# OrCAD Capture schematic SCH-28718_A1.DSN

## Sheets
1 1. Title Page: title: FRDM-KV10Z; rev: A1; company: Freescale Semiconductor; note: SCH-28718 | PDF: SPF-28718; note: 6501 William Cannon Drive West; note: Austin, TX 78735-8598
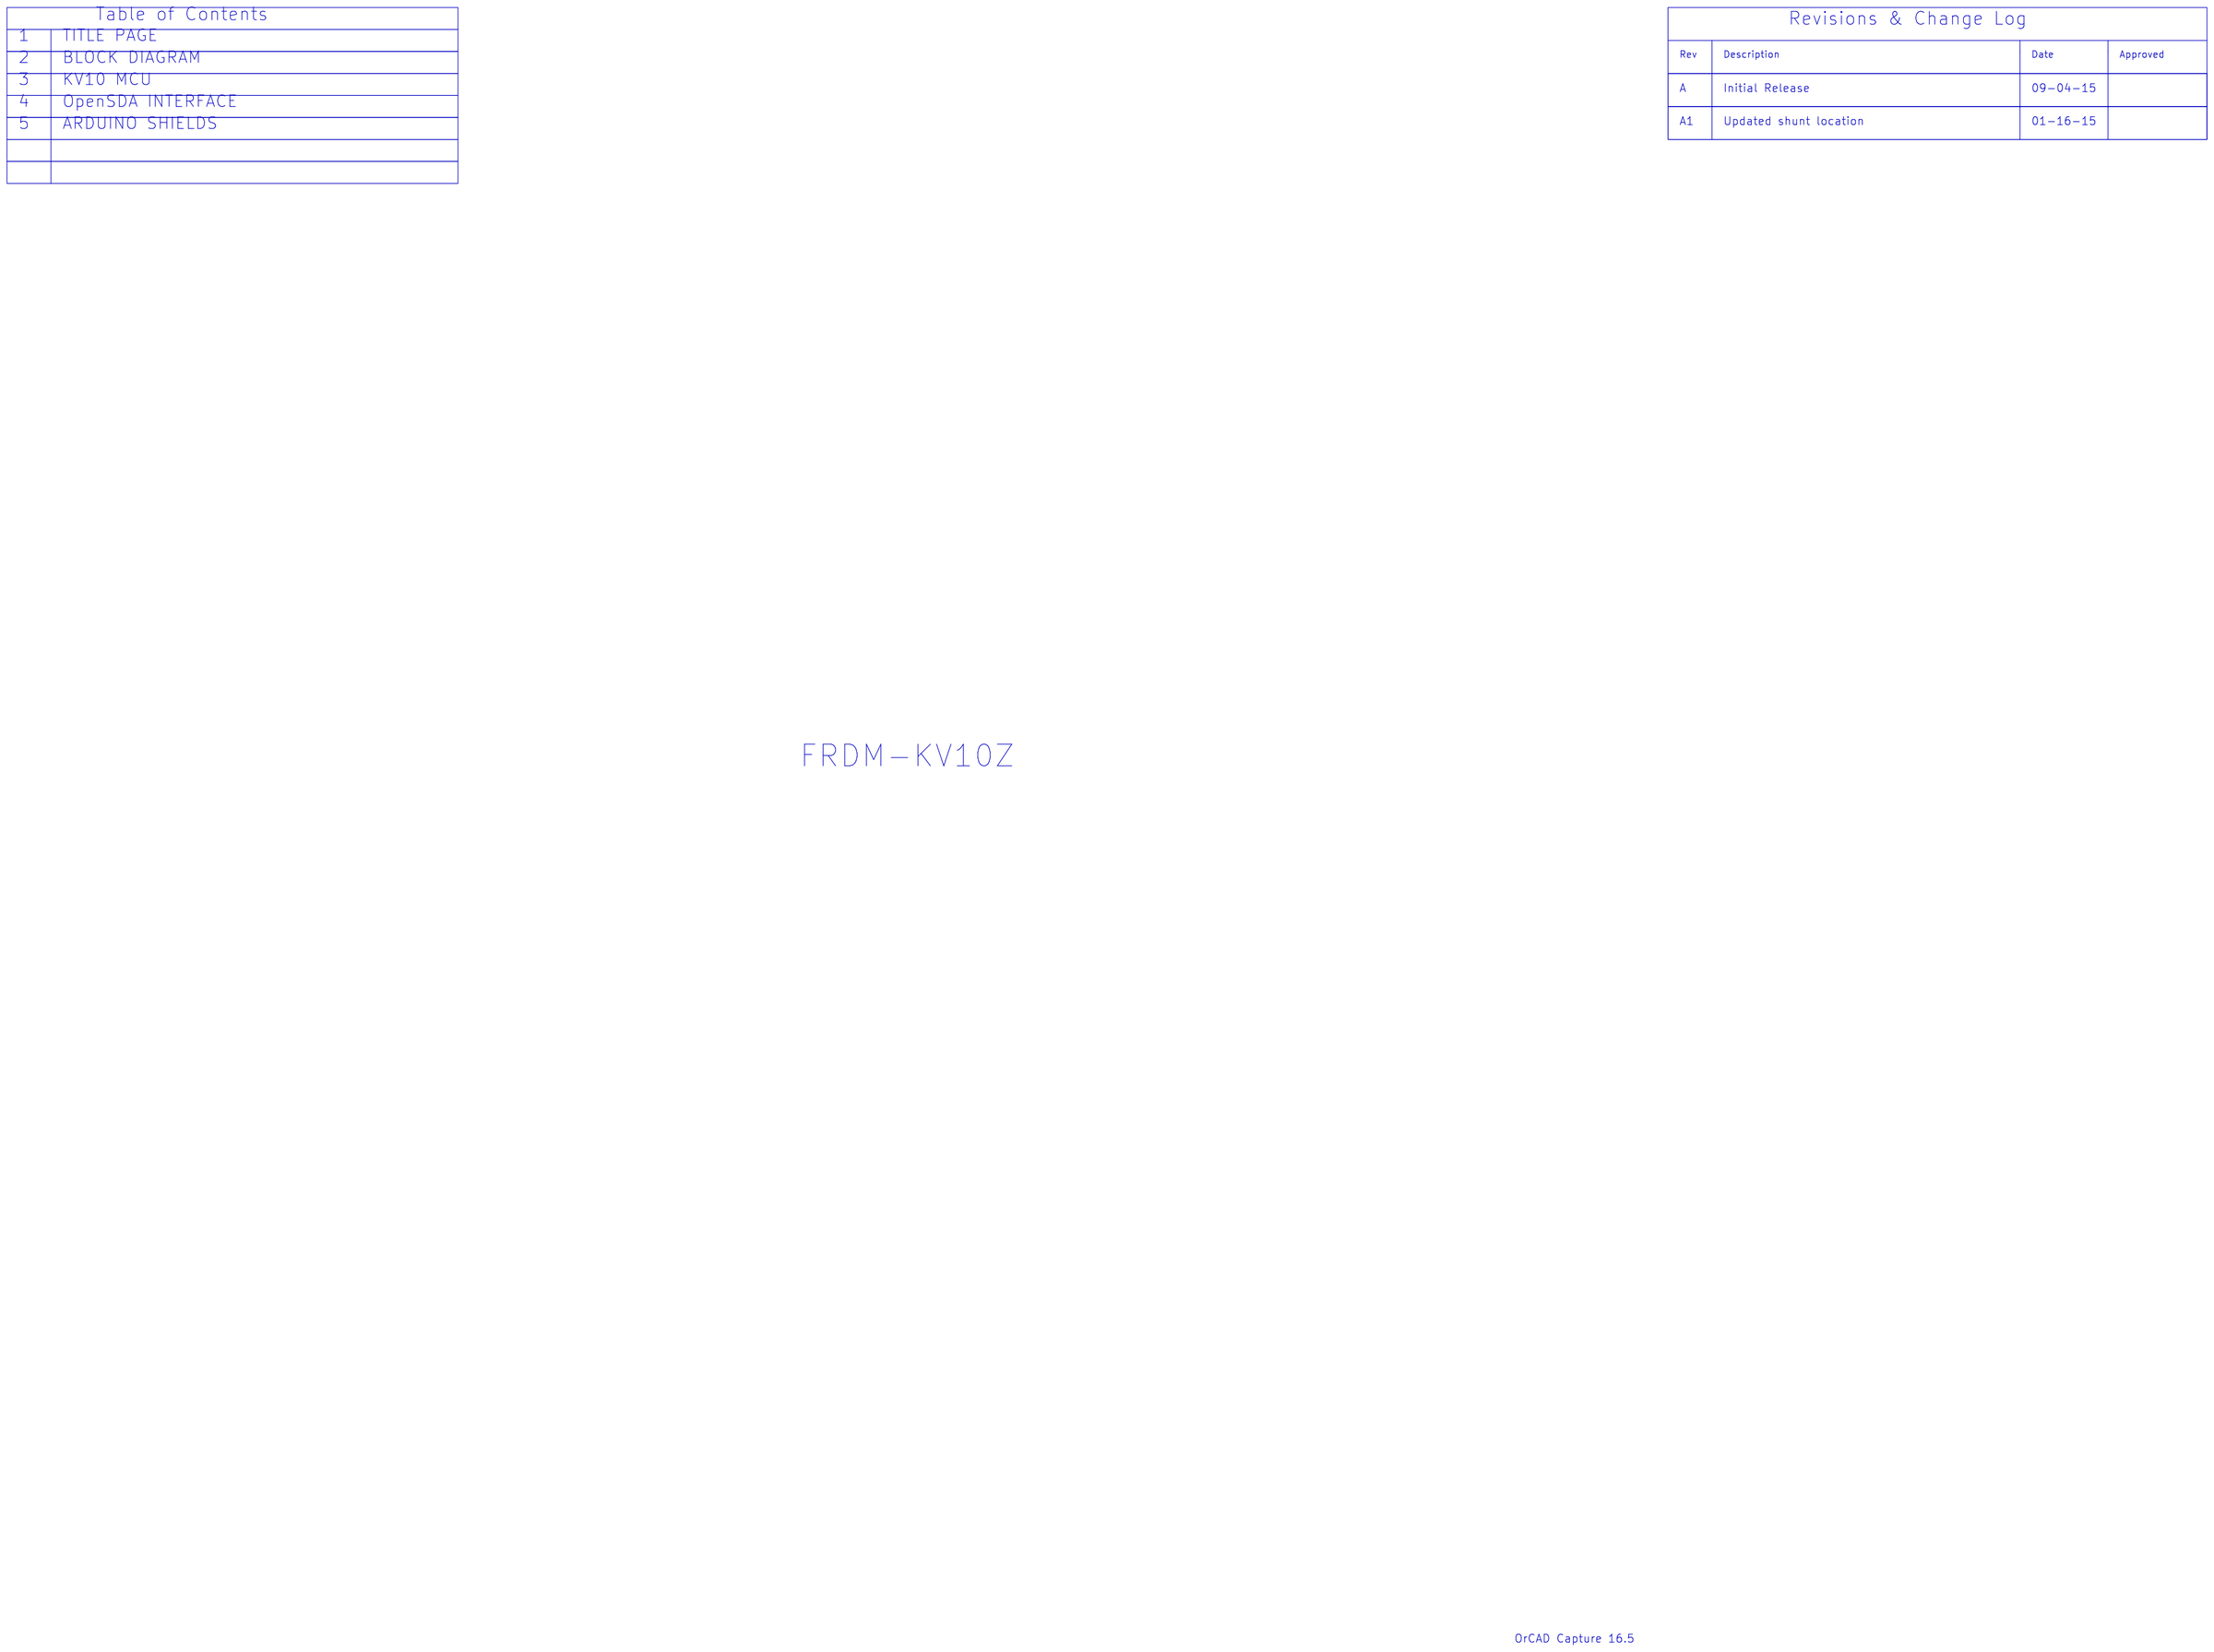
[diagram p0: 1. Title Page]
2 2. Block Diagram
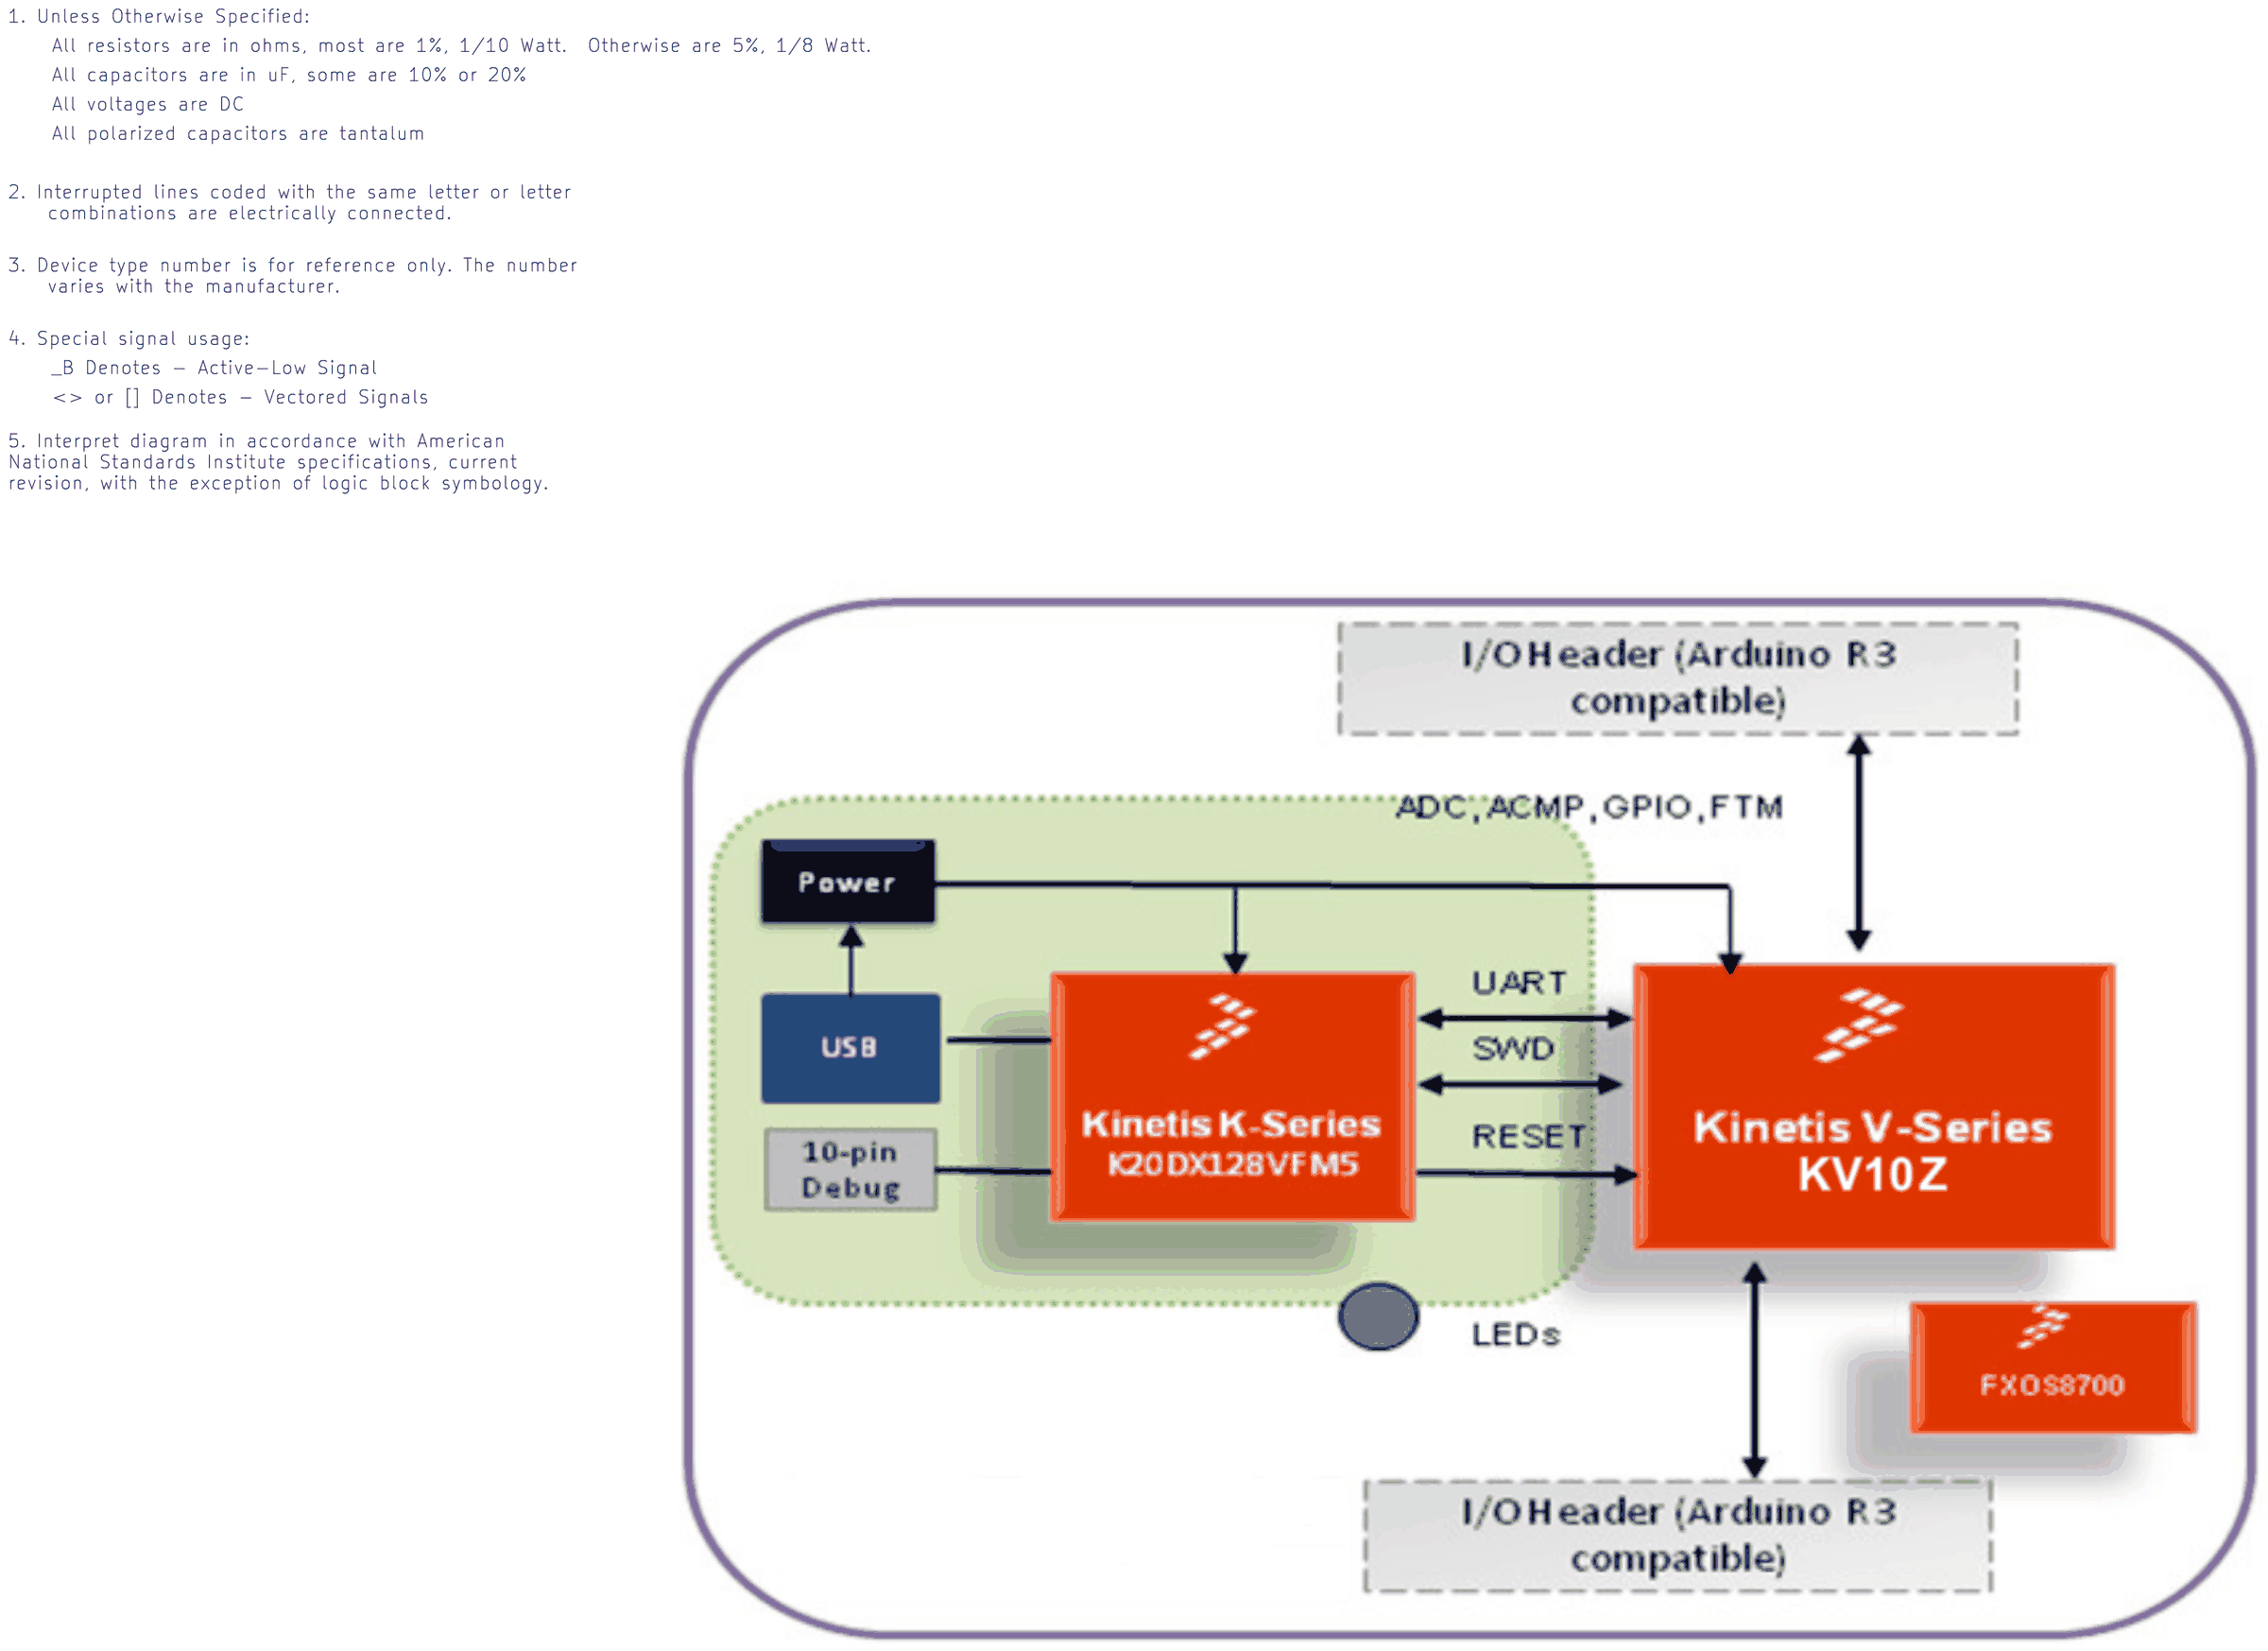
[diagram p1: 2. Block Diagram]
3 3. KV10 MCU: size C
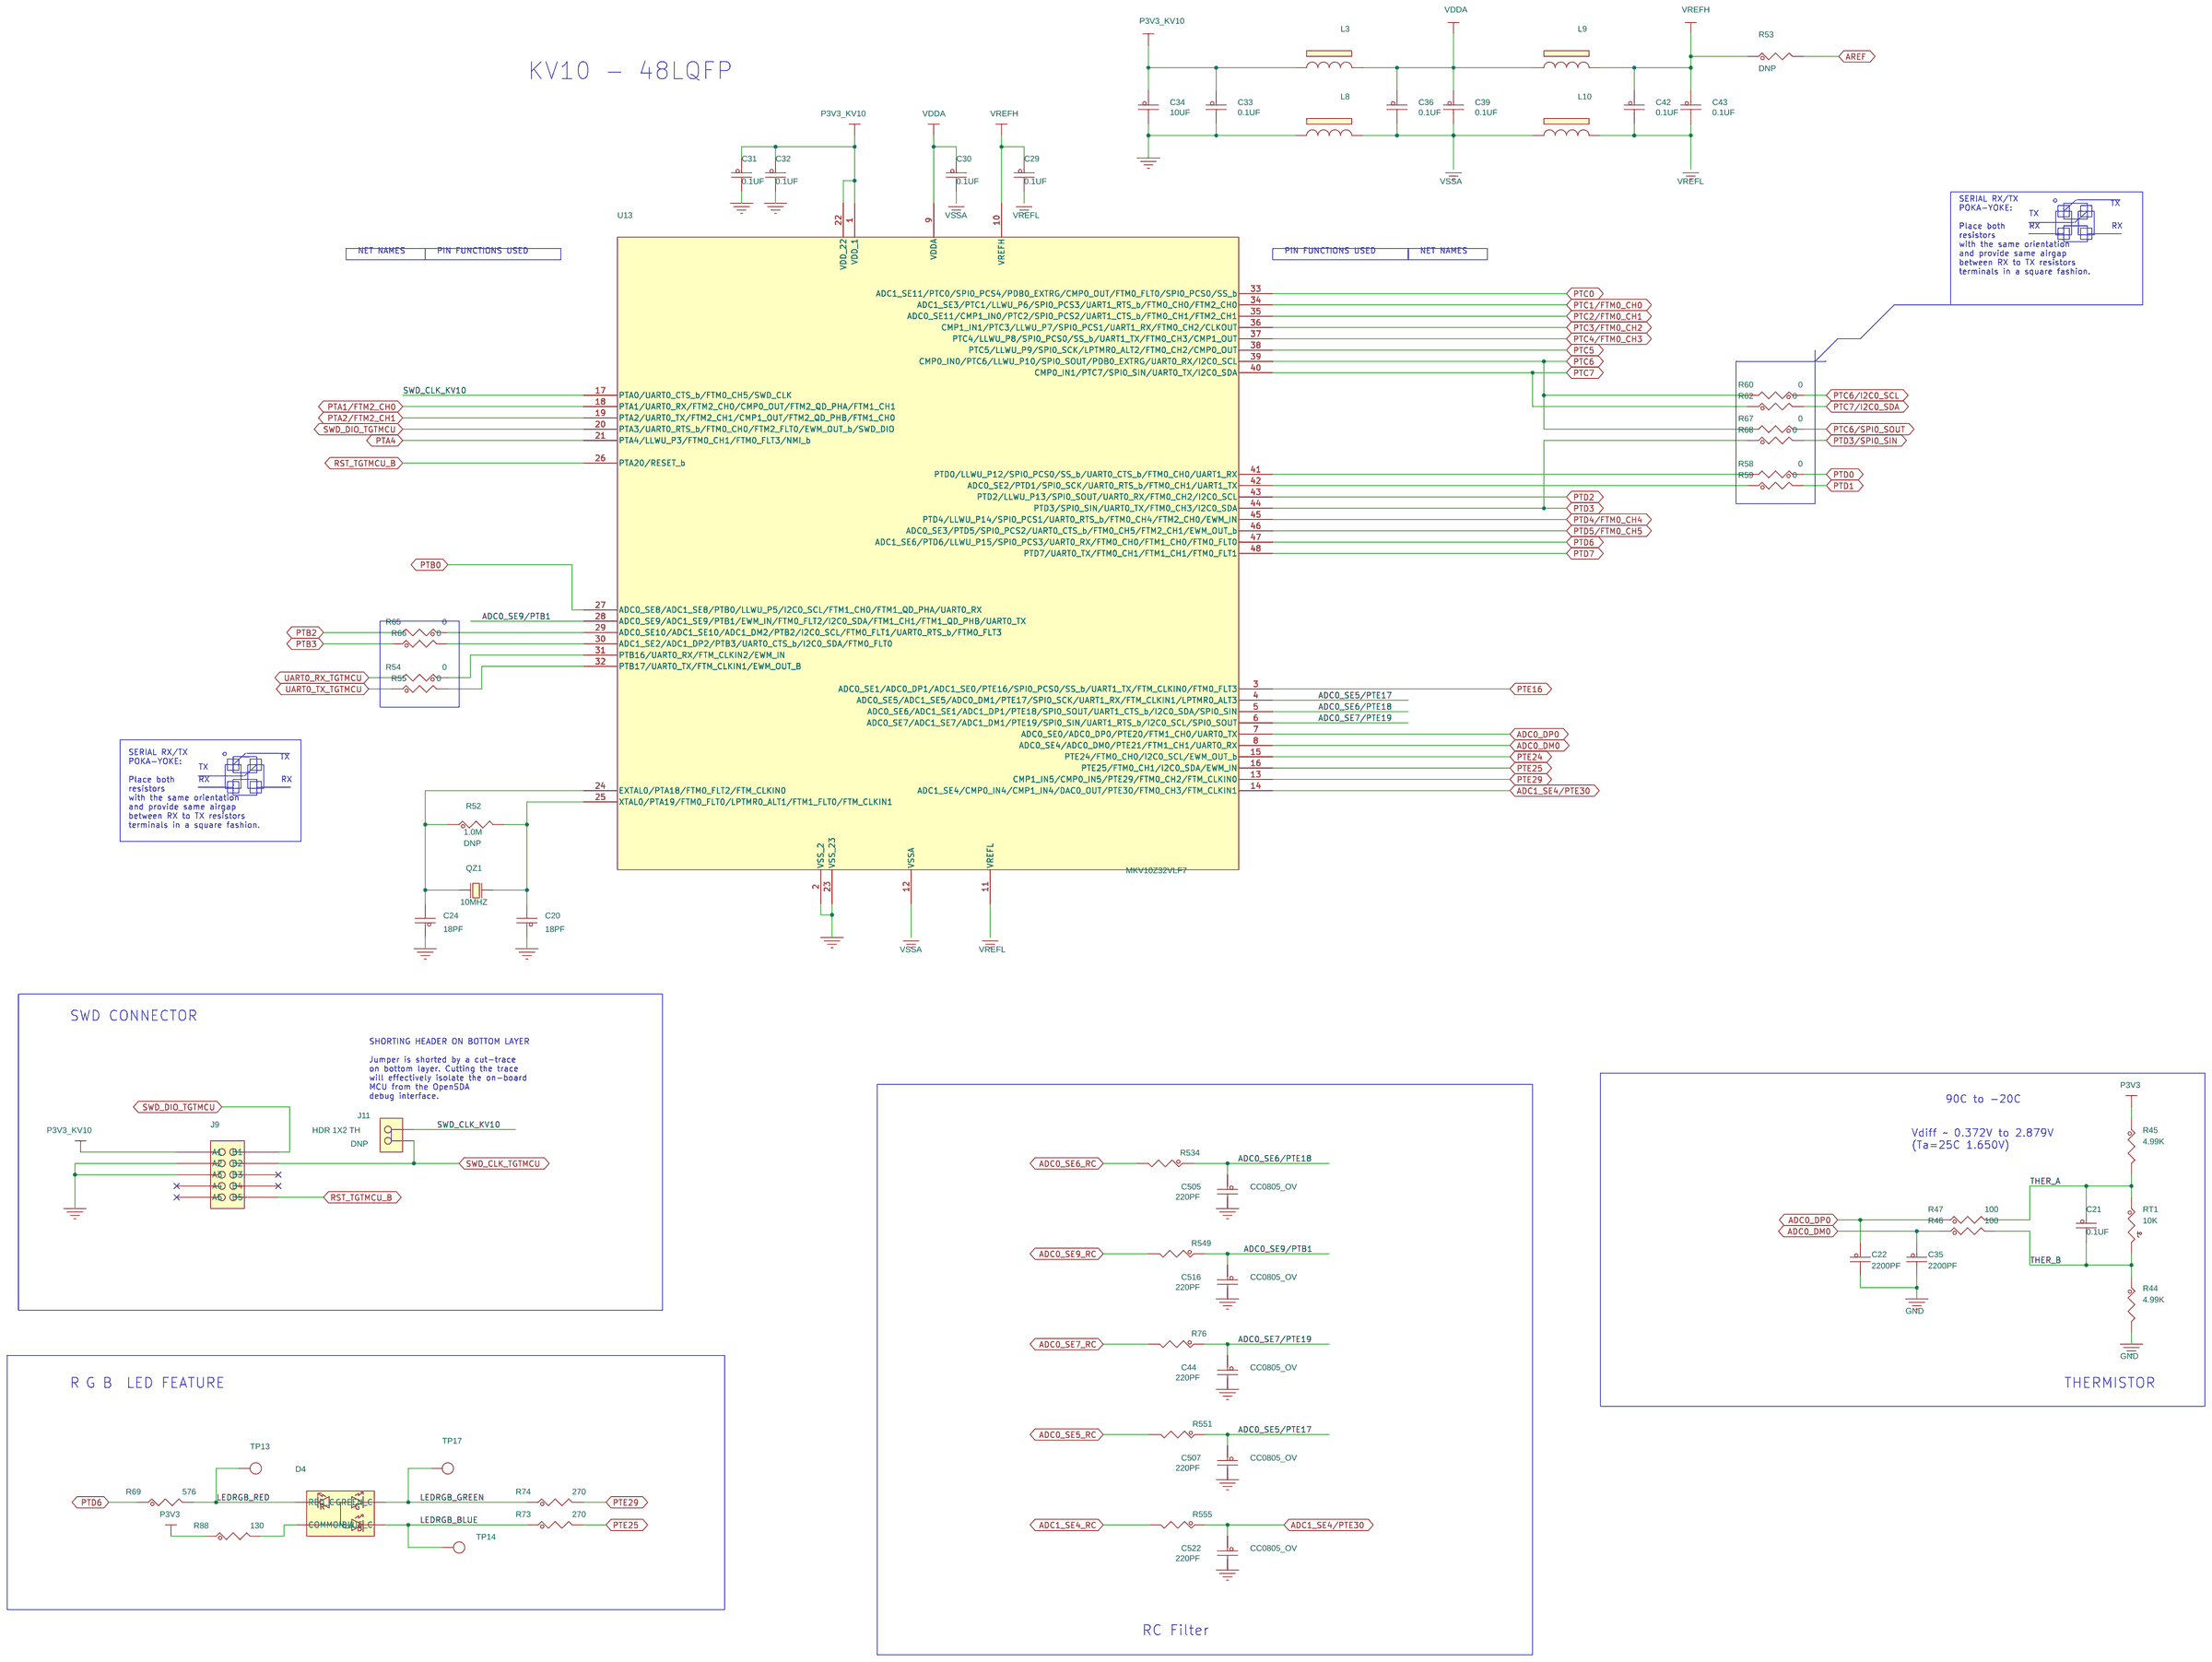
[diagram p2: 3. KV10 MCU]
4 4. OpenSDA interface: size D
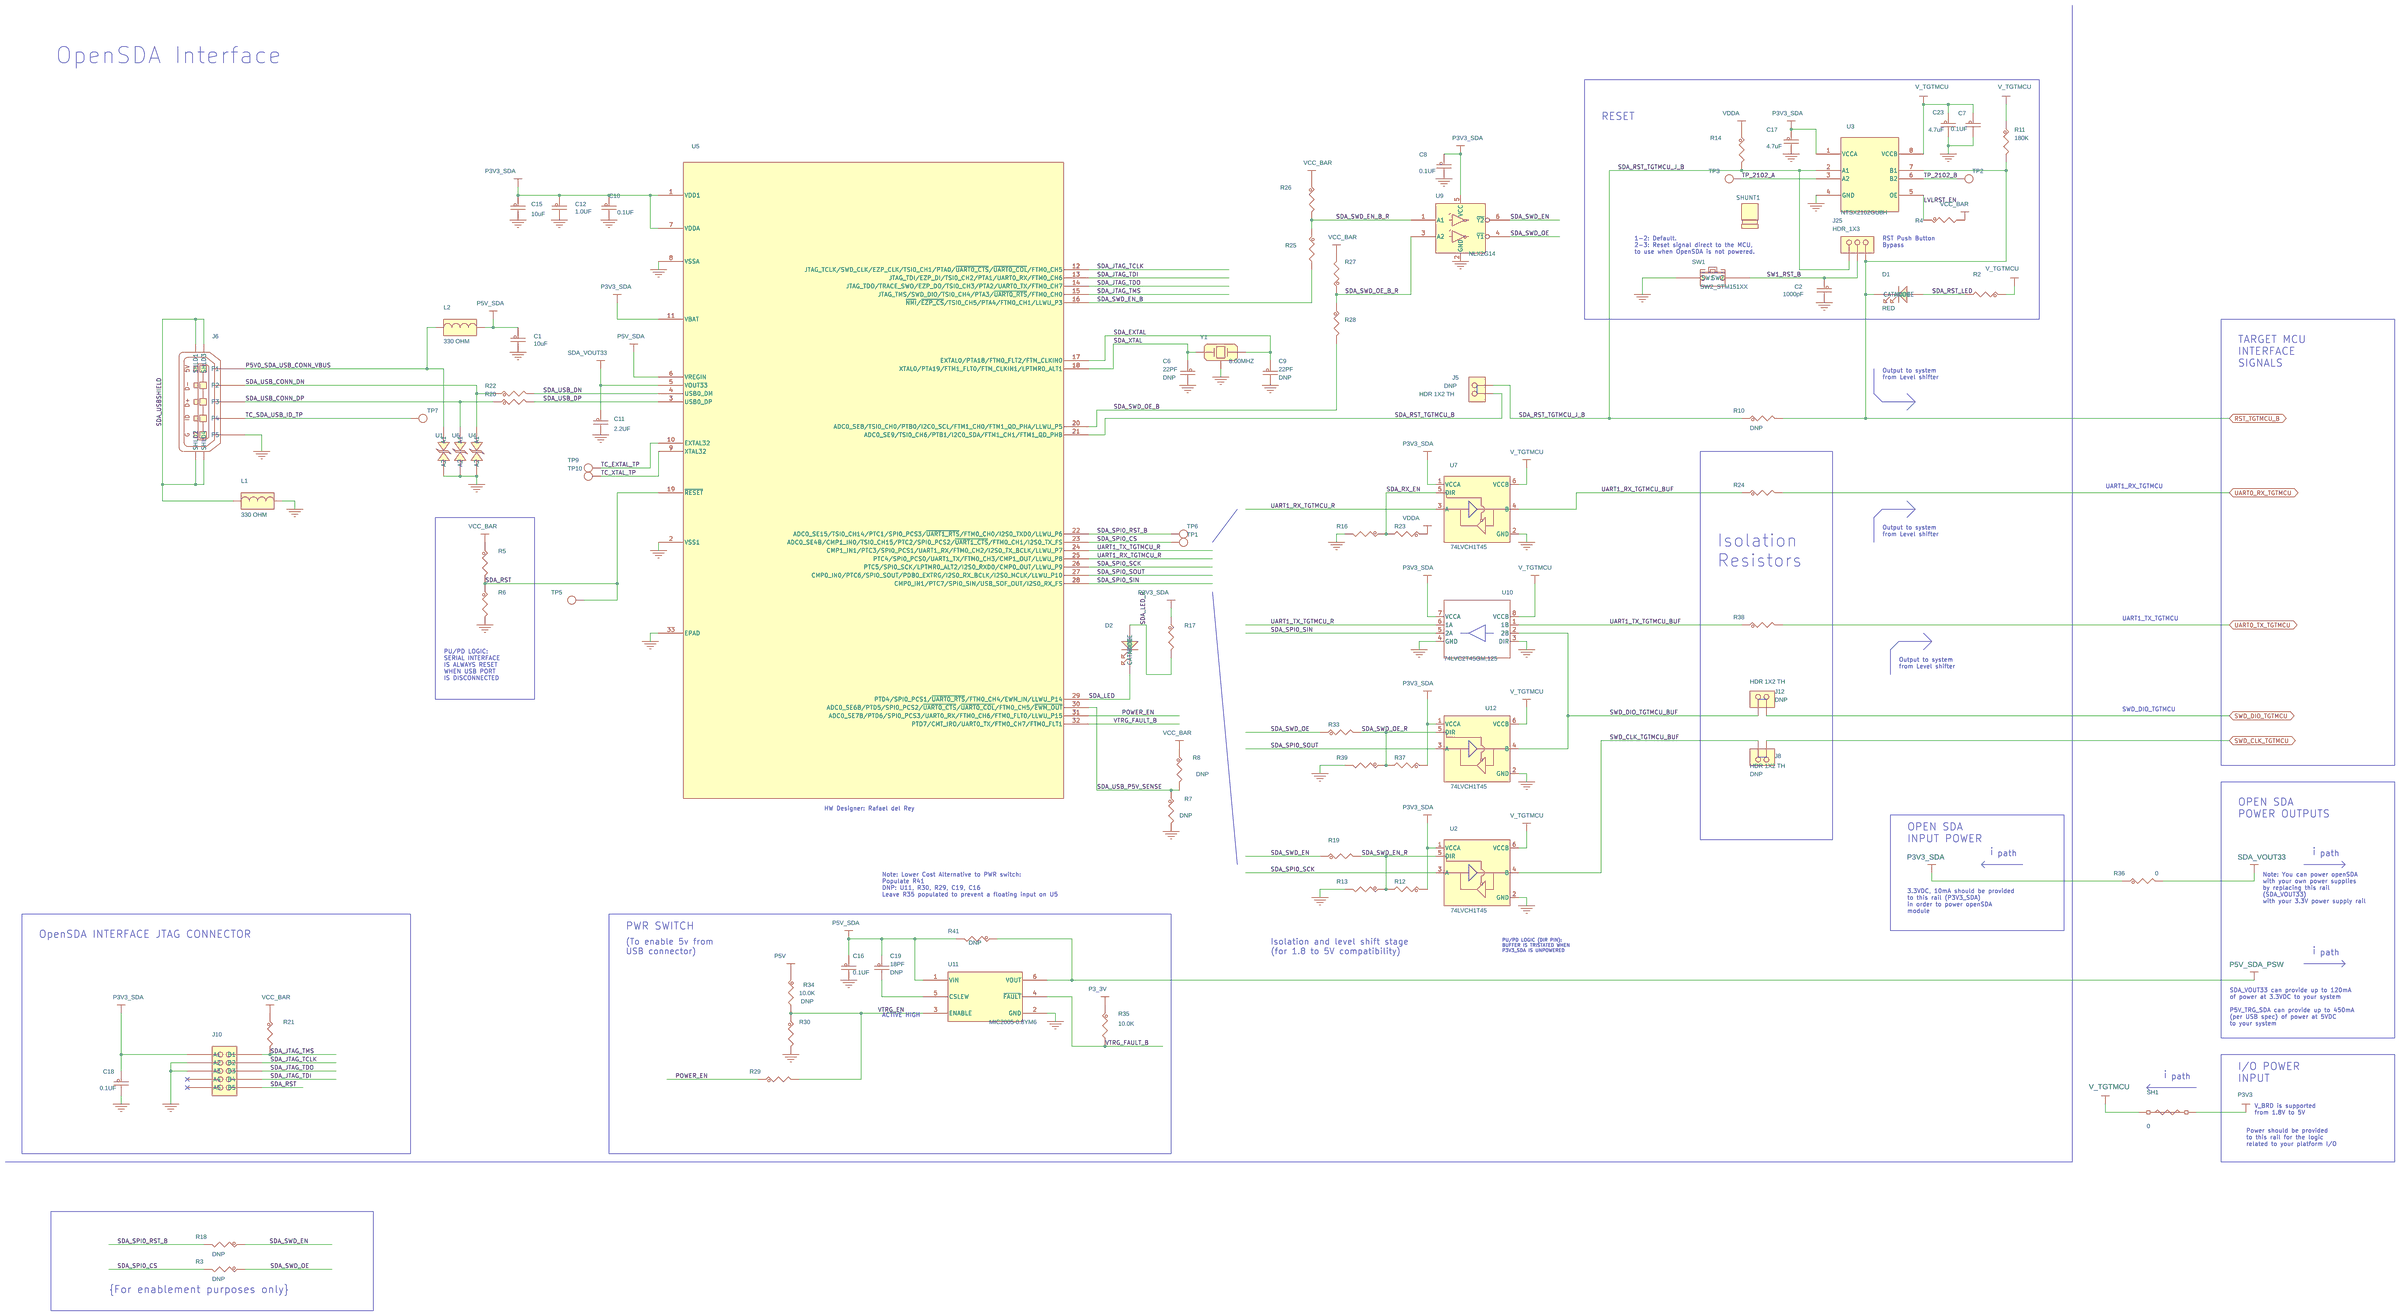
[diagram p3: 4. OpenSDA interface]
5 5. ARDUINO SHIELDS&COMBO SENSOR: size C
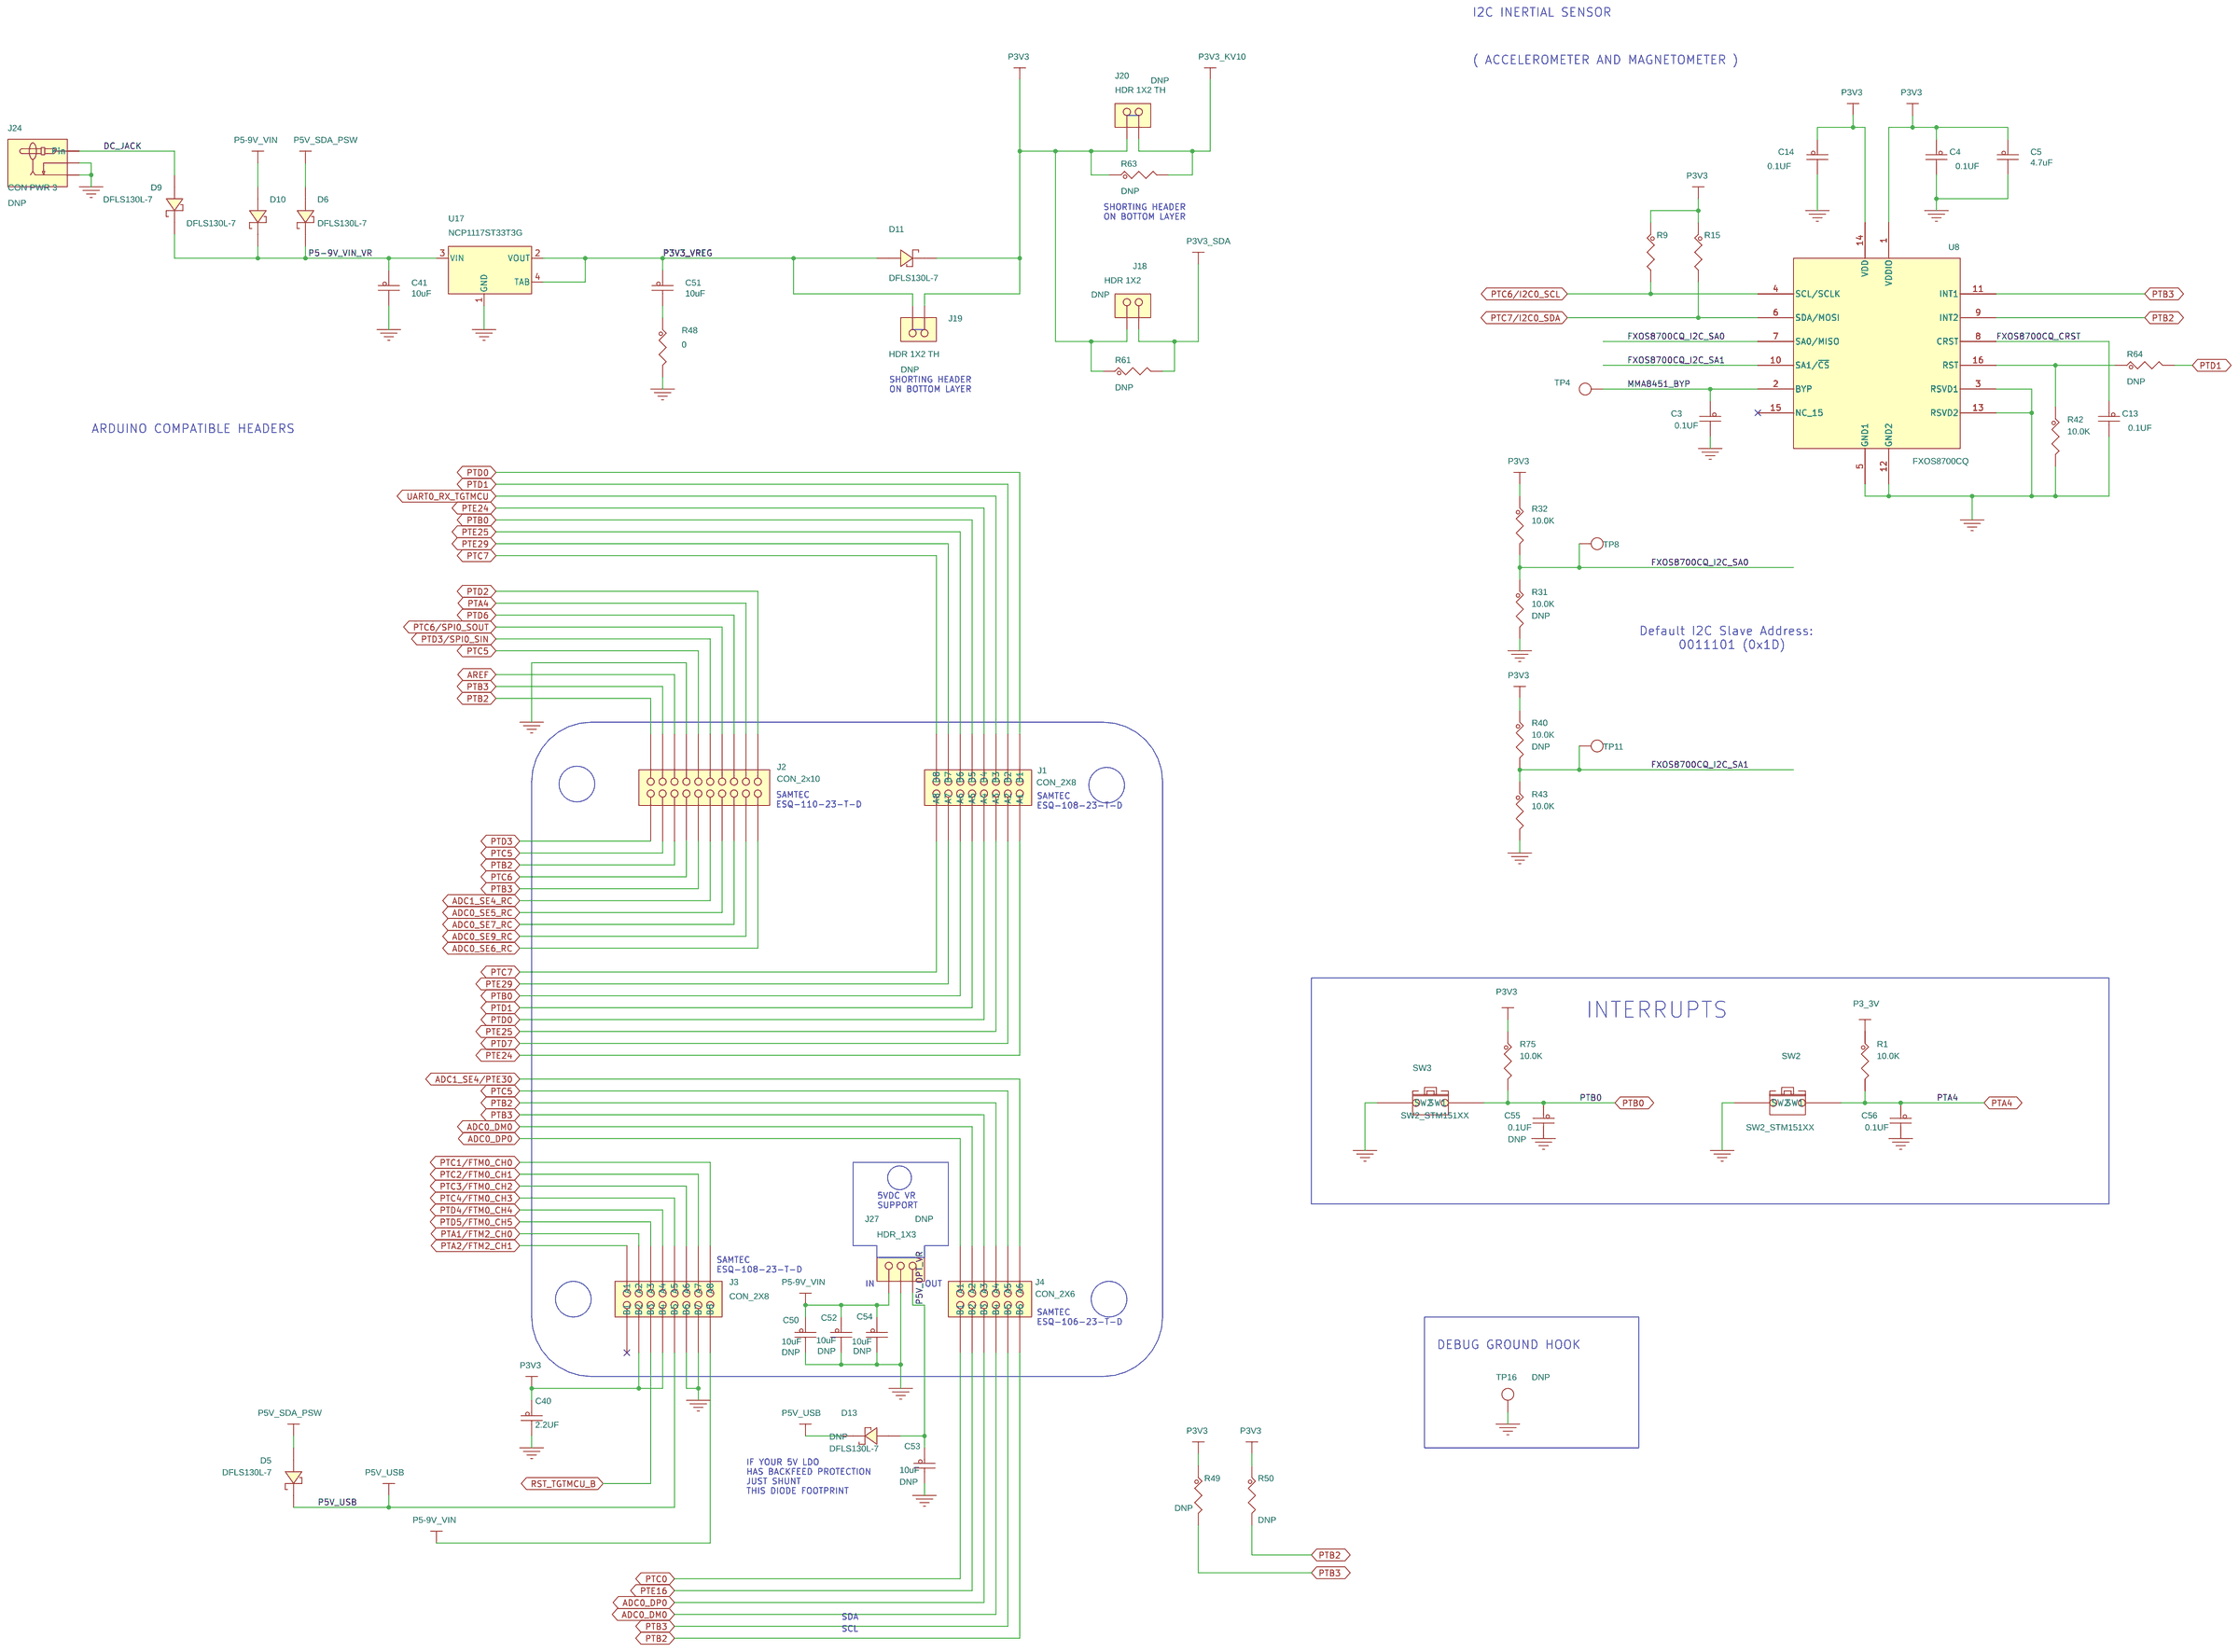
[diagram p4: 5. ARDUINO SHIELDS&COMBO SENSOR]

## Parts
sheet 3. KV10 MCU
C20  18PF  [CC0603_OV]
C21  0.1UF  [CC0402_25]
C22  2200PF  [CC0402_25]
C24  18PF  [CC0603_OV]
C29  0.1UF  [CC0402_25]
C30  0.1UF  [CC0402_25]
C31  0.1UF  [CC0402_25]
C32  0.1UF  [CC0402_25]
C33  0.1UF  [CC0603_OV]
C34  10UF  [CC0805_OV]
C35  2200PF  [CC0402_25]
C36  0.1UF  [CC0603_OV]
C39  0.1UF  [CC0603_OV]
C42  0.1UF  [CC0603_OV]
C43  0.1UF  [CC0603_OV]
C44  220PF  [CC0805_OV]
C505  220PF  [CC0805_OV]
C507  220PF  [CC0805_OV]
C516  220PF  [CC0805_OV]
C522  220PF  [CC0805_OV]
D4  CLV1A-FKB-CJ1M1F1BB7R4S3  [led4_3p4x3mm_smt]
J9  HDR 2X5  [hdr_5X2_ftsh_th_nsp]
J11  HDR 1X2 TH  [SH_HDR102_BOTTOM]
L3  1000@100MHZ  [IND_0805]
L8  1000@100MHZ  [IND_0805]
L9  1000@100MHZ  [IND_0805]
L10  1000@100MHZ  [IND_0805]
QZ1  10MHZ  [XTAL2-216X60-HCM49]
R44  4.99K  [RC0603_OV]
R45  4.99K  [RC0603_OV]
R46  100  [RC0402_25]
R47  100  [RC0402_25]
R52  1.0M  [RC0603_OV]
R53  0  [RC0402_25]
R54  0  [RC0402_25]
R55  0  [RC0402_25]
R58  0  [RC0402_25]
R59  0  [RC0402_25]
R60  0  [RC0402_25]
R62  0  [RC0402_25]
R65  0  [RC0402_25]
R66  0  [RC0402_25]
R67  0  [RC0402_25]
R68  0  [RC0402_25]
R69  576  [RC0402_25]
R73  270  [RC0402_25]
R74  270  [RC0402_25]
R76  100  [RC0402_25]
R88  130  [RC0402_25]
R534  100  [RC0402_25]
R549  100  [RC0402_25]
R551  100  [RC0402_25]
R555  100  [RC0402_25]
RT1  10K  [RC0603_OV]
TP13  TPAD_030  [TPAD_030]
TP14  TPAD_030  [TPAD_030]
TP17  TPAD_030  [TPAD_030]
U13  MKV10Z32VLF7  [QFP50P900X900X160-48N]
sheet 4. OpenSDA interface
C1  10uF  [CC0402_25]
C2  1000pF  [CC0402_25]
C6  22PF  [CC0402_25]
C7  0.1UF  [CC0402_25]
C8  0.1UF  [CC0402_25]
C9  22PF  [CC0402_25]
C10  0.1UF  [CC0402_25]
C11  2.2UF  [CC0603_OV]
C12  1.0UF  [CC0402_25]
C15  10uF  [CC0603_OV]
C16  0.1UF  [CC0402_25]
C17  4.7uF  [CC0402_25]
C18  0.1UF  [CC0402_25]
C19  18PF  [CC0603_OV]
C23  4.7uF  [CC0402_25]
D1  RED  [LED_0603]
D2  LED GREEN  [LED_0603]
J5  HDR 1X2 TH  [SH_HDR102_BOTTOM]
J6  MICRO USB AB 5  [con5_microusb]
J8  HDR 1X2 TH  [SH_HDR102_BOTTOM]
J10  HDR 2X5  [hdr_5X2_ftsh_th_nsp]
J12  HDR 1X2 TH  [SH_HDR102_BOTTOM]
J25  HDR_1X3  [HDR103]
L1  330 OHM  [ind_1608]
L2  330 OHM  [ind_1608]
R2  100  [RC0402_25]
R3  0  [RC0402_25]
R4  4.7K  [RC0402_25]
R5  4.7K  [RC0402_25]
R6  10.0K  [RC0402_25]
R7  10.0K  [RC0402_25]
R8  4.7K  [RC0402_25]
R10  0  [RC0402_25]
R11  180K  [RC0402_25]
R12  4.7K  [RC0402_25]
R13  10.0K  [RC0402_25]
R14  10.0K  [RC0402_25]
R16  10.0K  [RC0402_25]
R17  220  [RC0603_OV]
R18  0  [RC0402_25]
R19  0  [RC0402_25]
R20  33  [RC0402_25]
R21  10.0K  [RC0402_25]
R22  33  [RC0402_25]
R23  4.7K  [RC0402_25]
R24  0  [RC0402_25]
R25  0  [RC0402_25]
R26  10.0K  [RC0402_25]
R27  10.0K  [RC0402_25]
R28  0  [RC0402_25]
R29  1.0K  [RC0402_25]
R30  15K  [RC0402_25]
R33  0  [RC0402_25]
R34  10.0K  [RC0402_25]
R35  10.0K  [RC0402_25]
R36  0  [RC0603_OV]
R37  4.7K  [RC0402_25]
R38  0  [RC0402_25]
R39  10.0K  [RC0402_25]
R41  0  [RC0402_25]
SH1  0  [SH0603]
SHUNT1  SHUNT  [NONE]
SW1  SW2_STM151XX  [sw2_4x3mm_sm]
TP1  TPAD_030  [TPAD_030]
TP2  TPAD_030  [TPAD_030]
TP3  TPAD_030  [TPAD_030]
TP5  TPAD_030  [TPAD_030]
TP6  TPAD_030  [TPAD_030]
TP7  TPAD_030  [TPAD_030]
TP9  TPAD_030  [TPAD_030]
TP10  TPAD_030  [TPAD_030]
U1  0402ESDA-MLP  [0402_mlp]
U2  74LVCH1T45  [udfn6_1x1p5mm]
U3  NTSX2102GU8H  [xqfn8_1p45x1p25mm]
U4  0402ESDA-MLP  [0402_mlp]
U5  MK20DX128VFM5  [QFN32_S142EP]
U6  0402ESDA-MLP  [0402_mlp]
U7  74LVCH1T45  [udfn6_1x1p5mm]
U9  NLX2G14  [UDFN6_1p45x1_0p5mm]
U10  74LVC2T45GM,125  [qfn8_1p6x1p6mm]
U11  MIC2005-0.8YM6  [SOT23-6_a]
U12  74LVCH1T45  [udfn6_1x1p5mm]
Y1  8.00MHZ  [xtal3_3p35x1p45_sm]
sheet 5. ARDUINO SHIELDS&COMBO SENSOR
C3  0.1UF  [CC0402_25]
C4  0.1UF  [CC0402_25]
C5  4.7uF  [CC0603_OV]
C13  0.1UF  [CC0402_25]
C14  0.1UF  [CC0402_25]
C40  2.2UF  [CC0603_OV]
C41  10uF  [CC0603_OV]
C50  10uF  [CC0603_OV]
C51  10uF  [CC0603_OV]
C52  10uF  [CC0603_OV]
C53  10uF  [CC0603_OV]
C54  10uF  [CC0603_OV]
C55  0.1UF  [CC0402_25]
C56  0.1UF  [CC0402_25]
D5  DFLS130L-7  [powerdi-123_3mmx2mm]
D6  DFLS130L-7  [powerdi-123_3mmx2mm]
D9  DFLS130L-7  [powerdi-123_3mmx2mm]
D10  DFLS130L-7  [powerdi-123_3mmx2mm]
D11  DFLS130L-7  [powerdi-123_3mmx2mm]
D13  DFLS130L-7  [powerdi-123_3mmx2mm]
J1  CON_2X8  [HDR208_ESQ_SKT]
J2  CON_2x10  [hdr210_esq_skt]
J3  CON_2X8  [HDR208_ESQ_SKT]
J4  CON_2X6  [HDR206_ESQ_SKT]
J18  HDR 1X2  [hdr102]
J19  HDR 1X2 TH  [SH_HDR102_BOTTOM]
J20  HDR 1X2 TH  [SH_HDR102_BOTTOM]
J24  CON PWR 3  [con_jack_pj1_022_th-ra]
J27  HDR_1X3  [HDR103]
R1  10.0K  [RC0402_25]
R9  10.0K  [RC0402_25]
R15  10.0K  [RC0402_25]
R31  10.0K  [RC0402_25]
R32  10.0K  [RC0402_25]
R40  10.0K  [RC0402_25]
R42  10.0K  [RC0402_25]
R43  10.0K  [RC0402_25]
R48  0  [RC0603_OV]
R49  10.0K  [RC0402_25]
R50  10.0K  [RC0402_25]
R61  0  [RC0402_25]
R63  10  [RC0402_25]
R64  0  [RC0402_25]
R75  10.0K  [RC0402_25]
SW2  SW2_STM151XX  [sw2_4x3mm_sm]
SW3  SW2_STM151XX  [sw2_4x3mm_sm]
TP4  TPAD_030  [TPAD_030]
TP8  TPAD_030  [TPAD_030]
TP11  TPAD_030  [TPAD_030]
TP16  TEST POINT WHITE  [TEST_LOOP]
U8  FXOS8700CQ  [qfn5x3_0p5_3x3]
U17  NCP1117ST33T3G  [sot223]

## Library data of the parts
C20 C24 = CAP_NP: CAP CER 18PF 50V 5% C0G 0603; AGILE_PN: 150-75116; CAD_APPROVED: Yes; FPLIST: CC0603_OV,CC0603,0603_CC; HEIGHT: 0.90MM; MFG_NAME01: YAGEO AMERICA; MFG_PN01: CC0603JRNPO9BN180; ROHS: Yes; SIGNAL_MODEL: DEFAULT_CAPACITOR_1e+07pF_2_1; TOL: 5%; Tolerance: 5%; VOLTAGE: 50V
C21 C29-C32 = CAP_NP: CAP CER 0.1UF 10V 10% X5R 0402; AGILE_PN: 150-75634; CAD_APPROVED: Yes; FPLIST: CC0402_25,CC0402_HD,0402_CC; HEIGHT: 0.64MM; MFG_NAME01: KEMET; MFG_PN01: C0402C104K8PAC; ROHS: Yes; Tolerance: 10%; VOLTAGE: 10V
C22 C35 = CAP_NP: CAP CER 2200PF 50V 10%  X7R 0402; AGILE_PN: 150-75600; CAD_APPROVED: Yes; FPLIST: CC0402_25,CC0402_HD,0402_CC; HEIGHT: 0.55MM; MFG_NAME01: MURATA; MFG_PN01: GRM155R71H222KA01D; ROHS: Yes; Tolerance: 10%; VOLTAGE: 50V
C33 C36 C39 C42 C43 = CAP_NP: CAP CER 0.10UF 25V 10% X7R 0603; AGILE_PN: 150-75016; CAD_APPROVED: Yes; FPLIST: CC0603_OV,CC0603,0603_CC; HEIGHT: 0.97 MM; MFG_NAME01: KEMET; MFG_PN01: C0603C104K3RAC; ROHS: Yes; TOL: 10%; Tolerance: 10%; VOLTAGE: 25V
C34 = CAP_NP: CAP CER 10UF 16V 10% X5R 0805; AGILE_PN: 150-75283; CAD_APPROVED: Yes; FPLIST: CC0805_OV,CC0805,0805_CC; HEIGHT: 1.45MM; MFG_NAME01: AVX; MFG_PN01: 0805YD106KAT2A; ROHS: Yes; TOL: 10%; Tolerance: 10%; VOLTAGE: 16V
C44 C505 C507 C516 C522 = CAP_NP: CAP CER 220PF 50V 10% X7R 0805; AGILE_PN: 150-75217; CAD_APPROVED: YES; FPLIST: CC0805_OV,CC0805,0805_CC; HEIGHT: 1.4732MM; MFG_NAME01: VENKEL COMPANY; MFG_PN01: C0805X7R500-221KNE; ROHS: Yes; Tolerance: 10%; VOLTAGE: 50V
D4 = CLV1A_LED_4P: LED RED BL GRN SGL 50/25/25mA SMT; AGILE_PN: 370-76567; CAD_APPROVED: Yes; HEIGHT: 2.1MM; MFG_NAME01: CREE, INC; ROHS: Yes
J9 J10 = CONN_HDR_5X2: HDR 2X5 TH 50MIL CTR 167H AU 91L; AGILE_PN: 210-80192; CAD_APPROVED: Yes; FPLIST: hdr_5X2_ftsh_th,hdr_5X2_ftsh_th_nsp; HEIGHT: 4.25MM; MFG_NAME01: ANYTRONIC CORPORATION LIMITED; MFG_PN01: 0922S0205011N6T-2LF; ROHS: Yes
J5 J8 J11 J12 J19 J20 = CONN_HDR_2X1: HDR 1X2 TH 100MIL SP 339H AU 98L; AGILE_PN: 210-75439; ASSY_OPT: DNP; CAD_APPROVED: YES; FPLIST: HDR102,SH_HDR102_BOTTOM; HEIGHT: 8.71 MM; MFG_NAME01: SAMTEC; MFG_PN01: TSW-102-07-G-S; PRIORITY_PN: 028-00556; ROHS: Yes
L3 L8-L10 = INDUCTOR_FERRITE: IND FER BEAD 1000 OHM@100MHZ 200MA 25% 0805; AGILE_PN: 180-77479; CAD_APPROVED: Yes; FPLIST: IND_0805,0805_CC; HEIGHT: 1.05MM; MFG_NAME01: murata; MFG_PN01: BLM21AG102SN1B; PART_TYPE: INDUCTOR; ROHS: Yes; TOL: 25%; Tolerance: 25%
QZ1 = CRYSTAL: XTAL 10.0MHZ SER -- SMT; AGILE_PN: 230-75431; CAD_APPROVED: Yes; HEIGHT: 4.5MM; MFG_NAME01: CITIZEN; MFG_PN01: HCM49-10.000MABJ-UT; ROHS: Yes
R44 R45 = RES: RES MF 4.99K 1/10W 1% 0603; AGILE_PN: 470-75771; CAD_APPROVED: Yes; FPLIST: RC0603_OV,RC0603,0603_CC; MFG_NAME01: KOA SPEER; MFG_PN01: RK73H1JTTD4991F; ROHS: Yes; Tolerance: 1%
R46 R47 = RES: RES MF 100 OHM 1/16W 1% 0402; AGILE_PN: 470-30454; CAD_APPROVED: Yes; FPLIST: RC0402_25,RC0402_HD,0402_CC; MFG_NAME01: THYE MING TECH CO LTD; MFG_PN01: CR-02FL6--100R; ROHS: Yes; Tolerance: 1%
R52 = RES: RES MF 1.0M 1/10W 5% 0603; AGILE_PN: 470-75846; ASSY_OPT: DNP; CAD_APPROVED: Yes; FPLIST: RC0603_OV,RC0603,0603_CC; HEIGHT: 0.55MM; MFG_NAME01: BOURNS; MFG_PN01: CR0603-JW-105ELF; ROHS: Yes; TOL: 5%; Tolerance: 5%
R53 R61 R63 R64 = RES: RES MF ZERO OHM 1/16W 5% 0402; AGILE_PN: 470-75394; ASSY_OPT: DNP; CAD_APPROVED: Yes; FPLIST: RC0603_OV,RC0603,R603-X2,0603_CC; MFG_NAME01: ROHM; MFG_PN01: MCR01MZPJ000; PRIORITY_PN: 006-00559; ROHS: Yes; SIGNAL_MODEL: DEFAULT_RESISTOR_0.001OHM_2_1; Tolerance: 5%; VOLTAGE: 1/16W
R54 R55 R58-R60 R62 R65-R68 = RES: RES MF ZERO OHM 1/16W 5% 0402; AGILE_PN: 470-75394; CAD_APPROVED: Yes; FPLIST: RC0402_25,RC0402_HD,RC0402_X2,0402_CC; HEIGHT: 0.6MM; MFG_NAME01: ROHM; MFG_PN01: MCR01MZPJ000; ROHS: Yes; TOL: 1%; Tolerance: 5%
R69 = RES: RES MF 576 OHM 1/16W 1% 0402; AGILE_PN: 470-30813; CAD_APPROVED: Yes; FPLIST: RC0402_25,RC0402_HD,0402_CC; MFG_NAME01: KOA SPEER; MFG_PN01: RK73H1ETTP5760F; ROHS: Yes; Tolerance: 1%
R73 R74 = RES: RES MF 270 OHM 1/16W 5% 0402; AGILE_PN: 470-30332; CAD_APPROVED: Yes; FPLIST: RC0402_25,RC0402_HD,0402_CC; MFG_NAME01: VISHAY INTERTECHNOLOGY; MFG_PN01: CRCW0402270RJNED; ROHS: Yes; Tolerance: 5%
R76 R534 R549 R551 R555 = RES: RES MF 100 OHM 1/16W 5% 0402; AGILE_PN: 470-75591; CAD_APPROVED: Yes; FPLIST: RC0402_25,RC0402_HD,RC0402_X2,0402_CC; HEIGHT: 0.55 MM; MFG_NAME01: VENKEL COMPANY; MFG_PN01: CR040216W101JT; ROHS: Yes; TOL: 1%; Tolerance: 5%
R88 = RES: RES MF 130 OHM 1/16W 1% 0402; AGILE_PN: 470-30515; CAD_APPROVED: Yes; FPLIST: RC0402_25,RC0402_HD,0402_CC; MFG_NAME01: VISHAY INTERTECHNOLOGY; MFG_PN01: CRCW0402130RFKED; ROHS: Yes; Tolerance: 1%
RT1 = THERMISTOR: THERMISTOR 10K 1/10W 1% 0603; AGILE_PN: 470-80022; CAD_APPROVED: Yes; FPLIST: RC0603_OV,RC0603,0603_CC; MFG_NAME01: MuRata; MFG_PN01: NCP18XH103F03RB; ROHS: Yes; Tolerance: 1%
TP1-TP11 TP13 TP14 TP17 = TestLoop: TEST POINT PAD 30MIL DIA SMT, NO PART TO ORDER; AGILE_PN: 211-76642; CAD_APPROVED: Yes; HEIGHT: 0.1MM; MFG_NAME01: NOTACOMPONENT; MFG_PN01: NOTACOMPONENT; ROHS: Yes
U13 = MKV10Z32VLF7_LQFP48_6: IC MCU 32BIT 32KB FLASH 8KB RAM 75MHz 1.8-3.6V LQFP48; AGILE_PN: TMP-WF-18247; CAD_APPROVED: Yes; HEIGHT: 1.6 MM; MFG_NAME01: FREESCALE SEMICONDUCTOR; PRE_APN: 344-01641; ROHS: Yes
C1 = CAP_NP: CAP CER 10uF 10V 20% X5R 0402; AGILE_PN: 150-79255; CAD_APPROVED: Yes; FPLIST: C0402_25,CC0402_HD,0402_CC; HEIGHT: 0.7MM; MFG_NAME01: SAMSUNG; MFG_PN01: CL05A106MP5NUNC; PRIORITY_PN: 021-00242; ROHS: Yes; SIGNAL_MODEL: DEFAULT_CAPACITOR_1e+06pF_2_1; Tolerance: 20%; VOLTAGE: 10V
C2 = CAP_NP: CAP CER 1000PF 50V 5% C0G 0402; AGILE_PN: 150-76334; CAD_APPROVED: Yes; FPLIST: CC0402_25,CC0402_HD,0402_CC; HEIGHT: 0.55MM; MFG_NAME01: MURATA; MFG_PN01: GRM1555C1H102JA01D; ROHS: Yes; Tolerance: 5%; VOLTAGE: 50V
C6 C9 = CAP_NP: CAP CER 22PF 50V 5% C0G 0402; AGILE_PN: 150-75266; ASSY_OPT: DNP; CAD_APPROVED: Yes; FPLIST: CC0402_25,CC0402_HD,0402_CC; HEIGHT: 0.635MM; MFG_NAME01: AVX; MFG_PN01: 04025A220JAT2A; PRIORITY_PN: 021-00234; ROHS: Yes; SIGNAL_MODEL: DEFAULT_CAPACITOR_22.000000pF_2_1; Tolerance: 5%; VOLTAGE: 50V
C7 C8 C10 C16 C18 = CAP_NP: CAP CER 0.1UF 10V 10% X5R 0402; AGILE_PN: 150-75634; CAD_APPROVED: Yes; FPLIST: CC0402_25,CC0402_HD,0402_CC; HEIGHT: 0.64MM; MFG_NAME01: KEMET; MFG_PN01: C0402C104K8PAC; PRIORITY_PN: 021-00169; ROHS: Yes; SIGNAL_MODEL: DEFAULT_CAPACITOR_100000pF_2_1; TOL: 10%; Tolerance: 10%; VOLTAGE: 10V
C11 C40 = CAP_NP: CAP CER 2.2UF 10V 10% X7R 0603; AGILE_PN: 150-78564; CAD_APPROVED: Yes; FPLIST: CC0603_OV,CC0603,0603_CC; HEIGHT: 1.25MM; MFG_NAME01: TAIYO YUDEN; MFG_PN01: LMK107B7225KA-T; ROHS: Yes; SIGNAL_MODEL: DEFAULT_CAPACITOR_2.2e+06pF_2_1; Tolerance: 10%; VOLTAGE: 10V
C12 = CAP_NP: CAP CER 1.0UF 10V 10% X5R 0402; AGILE_PN: 150-75772; CAD_APPROVED: Yes; FPLIST: CC0402_25,CC0402_HD,0402_CC; HEIGHT: 0.6MM; MFG_NAME01: YAGEO AMERICA; MFG_PN01: CC0402KRX5R6BB105; PRIORITY_PN: 021-00242; ROHS: Yes; SIGNAL_MODEL: DEFAULT_CAPACITOR_1e+06pF_2_1; VOLTAGE: 10V
C15 = CAP_NP: CAP CER 10uF 16V 20% X5R 0603; AGILE_PN: 150-79092; CAD_APPROVED: Yes; FPLIST: CC0603_OV,CC0603,0603_CC; HEIGHT: 1mm; MFG_NAME01: TAIYO YUDEN; MFG_PN01: EMK107BBJ106MA-T; ROHS: Yes; SIGNAL_MODEL: DEFAULT_CAPACITOR_1e+07pF_2_1; TOL: 10%; Tolerance: 20%; VOLTAGE: 16V
C17 C23 = CAP_NP: CAP CER 4.7UF 6.3V 20% X5R 0402; AGILE_PN: 150-78463; CAD_APPROVED: Yes; FPLIST: CC0402_25,CC0402_HD,0402_CC; HEIGHT: 0.65MM; MFG_NAME01: VENKEL COMPANY; MFG_PN01: C0402X5R6R3-475MNP; PRIORITY_PN: 021-00169; ROHS: Yes; SIGNAL_MODEL: DEFAULT_CAPACITOR_4.7e+06pF_2_1; TOL: 10%; Tolerance: 20%; VOLTAGE: 6.3V
C19 = CAP_NP: CAP CER 18PF 50V 5% C0G 0603; AGILE_PN: 150-75116; ASSY_OPT: DNP; CAD_APPROVED: Yes; FPLIST: CC0603_OV,CC0603,0603_CC; HEIGHT: 0.90MM; MFG_NAME01: YAGEO AMERICA; MFG_PN01: CC0603JRNPO9BN180; PRIORITY_PN: 021-00320; ROHS: Yes; SIGNAL_MODEL: DEFAULT_CAPACITOR_18.000000pF_2_1; TOL: 5%; Tolerance: 5%; VOLTAGE: 50V
D1 = LED: LED ULTRA BRIGHT RED SGL 30MA 0603; AGILE_PN: 370-75079; CAD_APPROVED: Yes; HEIGHT: 0.9MM; MFG_NAME01: LITE ON; MFG_PN01: LTST-C190KRKT; ROHS: Yes
D2 = LED: LED GRN SGL 20MA 0603; AGILE_PN: 370-76565; CAD_APPROVED: Yes; HEIGHT: 0.67MM; MFG_NAME01: osram; MFG_PN01: LG L29K-G2J1-24-Z; ROHS: Yes
J6 = USB_MINI_AB_RECEPTACLE: CON 1X5 USB_MICRO_AB_RECEPTACLE RA SMT 0.65MM SP 105H AU; AGILE_PN: 211-78722; CAD_APPROVED: Yes; HEIGHT: 2.65MM; MFG_NAME01: Molex; MFG_PN01: 47589-0001; ROHS: Yes
J25 = CONN_HDR_3X1: HDR 1X3 TH 100MIL SP 330H AU 98L; AGILE_PN: 210-75442; CAD_APPROVED: Yes; HEIGHT: 8.38 MM; MFG_NAME01: SAMTEC; MFG_PN01: HTSW-103-07-S-S; PRIORITY_PN: 028-00700; ROHS: Yes
L1 L2 = BEAD: IND FER BEAD 330OHM@100MHZ 1.7A 0603; AGILE_PN: 180-78156; CAD_APPROVED: Yes; FPLIST: ind_1608,0603_CC; HEIGHT: 0.95MM; MFG_NAME01: TDK; MFG_PN01: MPZ1608S331A; PART_TYPE: FERRITE\BEAD; ROHS: Yes; Tolerance: 25%
R2 = RES: RES MF 100 OHM 1/16W 5% 0402; AGILE_PN: 470-75591; CAD_APPROVED: Yes; FPLIST: RC0402_25,RC0402_HD,RC0402_X2,0402_CC; HEIGHT: 0.55 MM; MFG_NAME01: VENKEL COMPANY; MFG_PN01: CR040216W101JT; ROHS: Yes; SIGNAL_MODEL: DEFAULT_RESISTOR_100.000000OHM_2_1; TOL: 1%; Tolerance: 5%
R3 R18 R41 = RES: RES MF ZERO OHM 1/16W 5% 0402; AGILE_PN: 470-75394; ASSY_OPT: DNP; CAD_APPROVED: Yes; FPLIST: RC0402_25,RC0402_HD,RC0402_X2,0402_CC; MFG_NAME01: ROHM; MFG_PN01: MCR01MZPJ000; PRIORITY_PN: 006-00559; ROHS: Yes; SIGNAL_MODEL: DEFAULT_RESISTOR_0.001OHM_2_1; Tolerance: 5%; VOLTAGE: 1/16W
R4 R5 R12 R23 R37 = RES: RES MF 4.7K 1/16W 5% 0402; AGILE_PN: 470-75626; CAD_APPROVED: Yes; FPLIST: RC0402_25,RC0402_HD,0402_CC; HEIGHT: 0.55 MM; MFG_NAME01: YAGEO AMERICA; MFG_PN01: RC0402JR-074K7L; ROHS: Yes; SIGNAL_MODEL: DEFAULT_RESISTOR_4700OHM_2_1; TOL: 1%; Tolerance: 5%
R6 R21 R32 R42 R43 = RES: RES MF 10.0K 1/16W 1% AEC-Q200 0402; AGILE_PN: 470-75416; CAD_APPROVED: Yes; FPLIST: RC0402_25,RC0402_HD,0402_CC; MFG_NAME01: VISHAY INTERTECHNOLOGY; MFG_PN01: CRCW040210K0FKED; PRIORITY_PN: 006-00552; ROHS: Yes; SIGNAL_MODEL: DEFAULT_RESISTOR_10000OHM_2_1; Tolerance: 1%
R7 R31 R40 = RES: RES MF 10.0K 1/16W 1% AEC-Q200 0402; AGILE_PN: 470-75416; ASSY_OPT: DNP; CAD_APPROVED: Yes; FPLIST: RC0402_25,RC0402_HD,0402_CC; MFG_NAME01: VISHAY INTERTECHNOLOGY; MFG_PN01: CRCW040210K0FKED; PRIORITY_PN: 006-00552; ROHS: Yes; SIGNAL_MODEL: DEFAULT_RESISTOR_10000OHM_2_1; Tolerance: 1%
R8 = RES: RES MF 4.7K 1/16W 5% 0402; AGILE_PN: 470-75626; ASSY_OPT: DNP; CAD_APPROVED: Yes; FPLIST: RC0402_25,RC0402_HD,0402_CC; HEIGHT: 0.55 MM; MFG_NAME01: YAGEO AMERICA; MFG_PN01: RC0402JR-074K7L; ROHS: Yes; SIGNAL_MODEL: DEFAULT_RESISTOR_4700OHM_2_1; TOL: 1%; Tolerance: 5%
R10 = RES: RES MF ZERO OHM 1/16W 5% 0402; AGILE_PN: 470-75394; ASSY_OPT: DNP; CAD_APPROVED: Yes; FPLIST: RC0402_25,RC0402_HD,RC0402_X2,0402_CC; HEIGHT: 0.45 MM; MFG_NAME01: ROHM; MFG_PN01: MCR01MZPJ000; PRIORITY_PN: 006-00559; ROHS: Yes; SIGNAL_MODEL: DEFAULT_RESISTOR_0.001OHM_2_1; TOL: 5%; Tolerance: 5%; VOLTAGE: 1/16W
R11 = RES: RES MF 180K  1/16W 1% 0402; AGILE_PN: 470-31088; CAD_APPROVED: Yes; FPLIST: RC0402_25,RC0402_HD,0402_CC; MFG_NAME01: KOA SPEER; MFG_PN01: RK73H1ETTP1803F; ROHS: Yes; SIGNAL_MODEL: DEFAULT_RESISTOR_180000OHM_2_1; Tolerance: 1%
R13 R14 R16 R26 R27 R39 = RES: RES MF 10.0K 1/16W 1% AEC-Q200 0402; AGILE_PN: 470-75416; CAD_APPROVED: Yes; FPLIST: RC0402_25,RC0402_HD,0402_CC; HEIGHT: 0.55MM; MFG_NAME01: VISHAY INTERTECHNOLOGY; MFG_PN01: CRCW040210K0FKED; PRIORITY_PN: 006-00552; ROHS: Yes; SIGNAL_MODEL: DEFAULT_RESISTOR_10000OHM_2_1; TOL: 5%; Tolerance: 1%
R17 = RES: RES MF 220 OHM 1/10W 5% 0603; AGILE_PN: 470-30297; CAD_APPROVED: Yes; FPLIST: RC0603_OV,RC0603,0603_CC; MFG_NAME01: KOA SPEER; MFG_PN01: RK73B1JTTD221J; ROHS: Yes; SIGNAL_MODEL: DEFAULT_RESISTOR_220.000000OHM_2_1; Tolerance: 5%
R19 R25 R28 R33 = RES: RES MF ZERO OHM 1/16W 5% 0402; AGILE_PN: 470-75394; CAD_APPROVED: Yes; FPLIST: RC0402_25,RC0402_HD,RC0402_X2,0402_CC; MFG_NAME01: ROHM; MFG_PN01: MCR01MZPJ000; PRIORITY_PN: 006-00559; ROHS: Yes; SIGNAL_MODEL: DEFAULT_RESISTOR_0.001OHM_2_1; Tolerance: 5%; VOLTAGE: 1/16W
R20 R22 = RES: RES MF 33.0 OHM 1/16W 1% 0402; AGILE_PN: 470-75790; CAD_APPROVED: Yes; FPLIST: RC0402_25,RC0402_HD,RC0402_X2,0402_CC; MFG_NAME01: THYE MING TECH CO LTD; MFG_PN01: CR-02FL6---33R; PRIORITY_PN: 006-00556; ROHS: Yes; SIGNAL_MODEL: DEFAULT_RESISTOR_33.000000OHM_2_1; Tolerance: 1%
R24 R38 = RES: RES MF ZERO OHM 1/16W 5% 0402; AGILE_PN: 470-75394; CAD_APPROVED: Yes; FPLIST: RC0402_25,RC0402_HD,RC0402_X2,0402_CC; HEIGHT: 0.45 MM; MFG_NAME01: ROHM; MFG_PN01: MCR01MZPJ000; PRIORITY_PN: 006-00559; ROHS: Yes; SIGNAL_MODEL: DEFAULT_RESISTOR_0.001OHM_2_1; TOL: 5%; Tolerance: 5%; VOLTAGE: 1/16W
R29 = RES: RES MF 1.0K 1/16W 1% 0402; AGILE_PN: 470-76037; CAD_APPROVED: Yes; FPLIST: RC0402_25,RC0402_HD,RC0402_X2,0402_CC; HEIGHT: 0.4MM; MFG_NAME01: YAGEO AMERICA; MFG_PN01: RC0402FR-071KL; PRIORITY_PN: 006-00553; ROHS: Yes; SIGNAL_MODEL: DEFAULT_RESISTOR_1000.000000OHM_2_1; TOL: 1%; Tolerance: 1%; VOLTAGE: 1/16W
R30 = RES: RES MF 15K  1/16W 1% 0402; AGILE_PN: 470-30965; CAD_APPROVED: Yes; FPLIST: RC0402_25,RC0402_HD,0402_CC; HEIGHT: 0.4 MM; MFG_NAME01: KOA SPEER; MFG_PN01: RK73H1ETTP1502F; ROHS: Yes; SIGNAL_MODEL: DEFAULT_RESISTOR_15000OHM_2_1; TOL: 1%; Tolerance: 1%
R34 R49 R50 = RES: RES MF 10.0K 1/16W 1% AEC-Q200 0402; AGILE_PN: 470-75416; ASSY_OPT: DNP; CAD_APPROVED: Yes; FPLIST: RC0402_25,RC0402_HD,0402_CC; HEIGHT: 0.4MM; MFG_NAME01: VISHAY INTERTECHNOLOGY; MFG_PN01: CRCW040210K0FKED; PRIORITY_PN: 006-00552; ROHS: Yes; SIGNAL_MODEL: DEFAULT_RESISTOR_10000OHM_2_1; TOL: 1%; Tolerance: 1%
R1 R15 R35 R75 = RES: RES MF 10.0K 1/16W 1% AEC-Q200 0402; AGILE_PN: 470-75416; CAD_APPROVED: Yes; FPLIST: RC0402_25,RC0402_HD,0402_CC; HEIGHT: 0.4MM; MFG_NAME01: VISHAY INTERTECHNOLOGY; MFG_PN01: CRCW040210K0FKED; PRIORITY_PN: 006-00552; ROHS: Yes; SIGNAL_MODEL: DEFAULT_RESISTOR_10000OHM_2_1; TOL: 1%; Tolerance: 1%
R36 R48 = RES: RES MF ZERO OHM 1/10W -- 0603; AGILE_PN: 470-75407; CAD_APPROVED: Yes; FPLIST: RC0603_OV,RC0603,R603-X2,0603_CC; MFG_NAME01: VISHAY INTERTECHNOLOGY; MFG_PN01: CRCW06030000Z0EA; ROHS: Yes; Tolerance: 1%
SH1 = RES_SHORT-2: ZERO OHM CUT TRACE 0603 PADS; NO PART TO ORDER; AGILE_PN: 470-80018; CAD_APPROVED: Yes; FPLIST: SH0603,SH0603_CC,SH0603-X2_PIN1TO2,SH0603-X2_PIN2TO3; MFG_NAME01: LAYOUT ELEMENT ONLY; MFG_PN01: LAYOUT ELEMENT ONLY; ROHS: Yes; SIGNAL_MODEL: DEFAULT_RESISTOR_0.001OHM_2_1
SHUNT1 = Shunt: SHUNT 2.54MM 2POS; ASSY_NOTE: J25.1 - J25.2; MFG_NAME01: 3M; MFG_PN01: 969102-0000-DA
SW1-SW3 = SW2_STM151XX: SW SPST MOM NO TACT 12V 50MA SMT; AGILE_PN: 510-76958; CAD_APPROVED: Yes; HEIGHT: 2MM; MFG_NAME01: E SWITCH; MFG_PN01: TL1015BF160QG; ROHS: Yes
U1 U4 U6 = DIODE_TVS_BIDIR: DIODE TVS BIDIR -- 30V 0402; AGILE_PN: 480-76179; CAD_APPROVED: Yes; HEIGHT: 0.44MM; MFG_NAME01: COOPER BUSSMANN; MFG_PN01: 0402ESDA-MLP1; PRIORITY_PN: 048-0402ESDA; ROHS: Yes
U2 U7 U12 = 74LVCH1T45_6P: IC XCVR 1BIT 3-STATE DUAL 1.2-5.5V XSON6; AGILE_PN: 312-80758; CAD_APPROVED: Yes; HEIGHT: 0.5MM; MFG_NAME01: NXP SEMICONDUCTORS; MFG_PN01: 74LVCH1T45GM,132; ROHS: Yes; VOLTAGE: 1.2-5.5V
U3 = NTSX2102GU8H_8P: IC DUAL SUPPLY XCVR 50 MBPS 5.5V XQFN8; AGILE_PN: 312-80763; CAD_APPROVED: Yes; HEIGHT: 0.5MM; MFG_NAME01: NXP Semiconductors; ROHS: Yes; VOLTAGE: 5.5V
U5 = PK20DX128V_QFN_32P: IC MCU FLASH 128KB 50MHZ 1.71-3.6V QFN32; AGILE_PN: 344-01231; CAD_APPROVED: Yes; HEIGHT: 1MM; MFG_NAME01: FREESCALE SEMICONDUCTOR; ROHS: Yes; VOLTAGE: 1.71-3.6V
U9 = NLU2GU04: IC INV DUAL SCHMITT TRIGGER 1.65-5.5V UDFN6; HEIGHT: 0.4MM; MFG_NAME01: On Semiconductor; MFG_PN01: NLX2G14AMUTCG; ROHS: Yes; VOLTAGE: 1.65-5.5V
U10 = 74LVC2T45GM_8P: IC XCVR DUAL SUPPLY 1.2 -5.5V XQFN8; AGILE_PN: 312-80762; CAD_APPROVED: Yes; HEIGHT: 0.5MM; MFG_NAME01: NXP Semiconductors; ROHS: Yes; VOLTAGE: 5.5V
U11 = MIC2005-0.8YM6: IC LIN SW PWR 0.8A 2.5-5.5V SOT23-6; AGILE_PN: 315-79199; CAD_APPROVED: Yes; HEIGHT: 1.45MM; MFG_NAME01: MICREL; PRIORITY_PN: 051-MIC2005-08; ROHS: Yes; VOLTAGE: 2.5-5.5V
Y1 = XTAL_CS: XTAL 8.00MHZ RSN CERAMIC -- SMT; AGILE_PN: 230-77664; CAD_APPROVED: Yes; HEIGHT: 0.8MM; MFG_NAME01: MURATA; MFG_PN01: CSTCE8M00G55-R0; PRIORITY_PN: 048-00290; ROHS: Yes
C3 C4 C13 C14 C56 = CAP_NP: CAP CER 0.1UF 10V 10% X5R 0402; AGILE_PN: 150-75634; CAD_APPROVED: Yes; FPLIST: CC0402_25,CC0402_HD,0402_CC; HEIGHT: 0.64MM; MFG_NAME01: KEMET; MFG_PN01: C0402C104K8PAC; PRIORITY_PN: 021-00169; ROHS: Yes; SIGNAL_MODEL: DEFAULT_CAPACITOR_100000pF_2_1; Tolerance: 10%; VOLTAGE: 10V
C5 = CAP_NP: CAP CER 4.7uF 16V 10% X5R 0603; AGILE_PN: 150-78976; CAD_APPROVED: Yes; FPLIST: CC0603_OV,CC0603,0603_CC; HEIGHT: 0.9 MM; MFG_NAME01: TDK; MFG_PN01: C1608X5R1C475K; ROHS: Yes; SIGNAL_MODEL: DEFAULT_CAPACITOR_4.7e+06pF_2_1; Tolerance: 10%; VOLTAGE: 16V
C41 = CAP_NP: CAP CER 10uF 16V 20% X5R 0603; AGILE_PN: 150-79092; CAD_APPROVED: Yes; FPLIST: CC0603_OV,CC0603,0603_CC; HEIGHT: 1mm; MFG_NAME01: TAIYO YUDEN; MFG_PN01: EMK107BBJ106MA-T; ROHS: Yes; SIGNAL_MODEL: DEFAULT_CAPACITOR_1e+07pF_2_1; Tolerance: 20%; VOLTAGE: 16V
C50 C52 C54 = CAP_NP: CAP CER 10uF 16V 20% X5R 0603; AGILE_PN: 150-79092; ASSY_OPT: DNP; CAD_APPROVED: Yes; FPLIST: CC0603_OV,CC0603,0603_CC; HEIGHT: 1mm; MFG_NAME01: TAIYO YUDEN; MFG_PN01: EMK107BBJ106MA-T; ROHS: Yes; SIGNAL_MODEL: DEFAULT_CAPACITOR_1e+07pF_2_1; Tolerance: 20%; VOLTAGE: 16V
C51 = CAP_NP: CAP CER 10UF 10V 20% X5R 0603; AGILE_PN: 150-78609; CAD_APPROVED: Yes; FPLIST: CC0603_OV,CC0603,0603_CC; HEIGHT: 1.016MM; MFG_NAME01: TAIYO YUDEN; MFG_PN01: LMK107BJ106MALTD; ROHS: Yes; SIGNAL_MODEL: DEFAULT_CAPACITOR_1e+07pF_2_1; VOLTAGE: 10V
C53 = CAP_NP: CAP CER 10UF 10V 20% X5R 0603; AGILE_PN: 150-78609; ASSY_OPT: DNP; CAD_APPROVED: Yes; FPLIST: CC0603_OV,CC0603,0603_CC; HEIGHT: 1.016MM; MFG_NAME01: TAIYO YUDEN; MFG_PN01: LMK107BJ106MALTD; ROHS: Yes; SIGNAL_MODEL: DEFAULT_CAPACITOR_1e+07pF_2_1; VOLTAGE: 10V
C55 = CAP_NP: CAP CER 0.1UF 10V 10% X5R 0402; AGILE_PN: 150-75634; ASSY_OPT: DNP; CAD_APPROVED: Yes; FPLIST: CC0402_25,CC0402_HD,0402_CC; HEIGHT: 0.64MM; MFG_NAME01: KEMET; MFG_PN01: C0402C104K8PAC; PRIORITY_PN: 021-00169; ROHS: Yes; SIGNAL_MODEL: DEFAULT_CAPACITOR_100000pF_2_1; Tolerance: 10%; VOLTAGE: 10V
D5 D6 D9-D11 = DIODE_SCHTKY: DIODE SCH 1A 30V PowerDI123; AGILE_PN: 480-78285; CAD_APPROVED: Yes; HEIGHT: 1MM; MFG_NAME01: DIODES INC; ROHS: Yes
D13 = DIODE_SCHTKY: DIODE SCH 1A 30V PowerDI123; AGILE_PN: 480-78285; ASSY_OPT: DNP; CAD_APPROVED: Yes; HEIGHT: 1MM; MFG_NAME01: DIODES INC; ROHS: Yes
J1 J3 = CONN_HDR_8X2: CON 2X8 SKT TH 100MIL CTR 545H SN 190L; AGILE_PN: 210-80538; CAD_APPROVED: Yes; HEIGHT: 13.843MM; MFG_NAME01: samtec; MFG_PN01: ESQ-108-23-T-D; ROHS: Yes
J2 = CONN_HDR_10X2: CON 2X10 SKT TH 100MIL CTR 540H SN 190L; AGILE_PN: 210-80537; CAD_APPROVED: Yes; HEIGHT: 13.72MM; MFG_NAME01: SAMTEC; MFG_PN01: ESQ-110-23-T-D; ROHS: Yes
J4 = CONN_HDR_6X2: CON 2X6 SKT TH 100MIL CTR 540H SN 190L; AGILE_PN: 210-80536; CAD_APPROVED: Yes; HEIGHT: 13.72MM; MFG_NAME01: SAMTEC; MFG_PN01: ESQ-106-23-T-D; ROHS: Yes
J18 = CONN_HDR_2X1: HDR 1X2 TH 100MIL SP 330H SN 115L; AGILE_PN: 210-76752; ASSY_OPT: DNP; CAD_APPROVED: Yes; HEIGHT: 8.58MM; MFG_NAME01: Samtec; MFG_PN01: TSW-102-23-T-S; ROHS: Yes
J24 = DC_POWER_JACK: CON 3 PWR JACK RA TH --- 201H AG 118L; AGILE_PN: 210-80316; ASSY_OPT: DNP; CAD_APPROVED: Yes; HEIGHT: 5.1MM; MFG_NAME01: CUI Inc; MFG_PN01: PJ1-022; ROHS: Yes
J27 = CONN_HDR_3X1: HDR 1X3 TH 100MIL SP 330H AU 98L; AGILE_PN: 210-75442; ASSY_OPT: DNP; CAD_APPROVED: Yes; HEIGHT: 8.38 MM; MFG_NAME01: SAMTEC; MFG_PN01: HTSW-103-07-S-S; PRIORITY_PN: 028-00700; ROHS: Yes
R9 = RES: RES MF 10.0K 1/16W 1% AEC-Q200 0402; AGILE_PN: 470-75416; CAD_APPROVED: Yes; FPLIST: RC0402_25,RC0402_HD,0402_CC; HEIGHT: 0.4MM; MFG_NAME01: VISHAY INTERTECHNOLOGY; MFG_PN01: CRCW040210K0FKED; PRIORITY_PN: 006-00552; ROHS: Yes; SIGNAL_MODEL: DEFAULT_RESISTOR_10000OHM_2_1; TOL: 1%; Tolerance: 5%
TP16 = TestLoop: TEST POINT WHITE 40 MIL DRILL 180 MIL TH 109L; AGILE_PN: 210-75685; ASSY_OPT: DNP; CAD_APPROVED: Yes; HEIGHT: 4.8 MM; MFG_NAME01: KEYSTONE ELECTRONICS; MFG_PN01: 5002; PRIORITY_PN: 028-00434; ROHS: Yes
U8 = FXOS8700CQ_QFN_16P: IC ACCELEROMETER AND MAGNETOMETER SENSOR 3-AXIS 2.5V QFN16; AGILE_PN: TMP-WF-16648; CAD_APPROVED: Yes; HEIGHT: 1.25MM; MFG_NAME01: Freescale Semiconductor; PRE_APN: 312-80418; ROHS: Yes; VOLTAGE: 2.5V
U17 = LD1117AS18: IC VREG LDO 1A 3.3V SOT223; AGILE_PN: 312-80039; CAD_APPROVED: Yes; HEIGHT: 1.8MM; MFG_NAME01: ON Semiconductor; ROHS: Yes

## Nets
GND: C1.2 C2.2 C3.2 C4.2 C5.2 C6.2 C7.2 C8.2 C9.2 C10.2 C11.2 C12.2 C13.2 C14.2 C15.2 C16.2 C17.2 C18.2 C20.1 C22.2 C23.2 C24.1 C31.2 C32.2 C33.2 C34.2 C35.2 C40.2 C41.2 C44.2 C50.2 C52.2 C53.2 C54.2 C55.2 C56.2 C505.2 C507.2 C516.2 C522.2 J2.14 J3.12(B6) J3.14(B7) J6.5(P5) J9.3(A2) J9.5(A3) J10.3(A2) J10.5(A3) J24.2 J24.3 J27.2 L1.2 L8.2 R6.2 R7.2 R13.2 R16.2 R30.2 R31.2 R39.2 R42.2 R43.2 R44.2 R48.2 SW1.1(SW1) SW2.2(SW2) SW3.2(SW2) TP16.1(Pin1) U1.2(A2) U2.2(GND) U3.4(GND) U4.2(A2) U5.2(VSS1) U5.8(VSSA) U5.33(EPAD) U6.2(A2) U7.2(GND) U8.3(RSVD1) U8.5(GND1) U8.12(GND2) U8.13(RSVD2) U9.2(GND) U10.3(DIR) U10.4(GND) U11.2(GND) U12.2(GND) U13.2(VSS) U13.23(VSS) U17.1(GND) Y1.2
P3V3: C4.1 C5.1 C14.1 C40.1 D11.C J3.4(B2) J3.8(B4) J18.2 J19.1 J20.1 R1.1 R9.1 R15.1 R32.1 R40.1 R45.1 R49.1 R50.1 R61.1 R63.1 R75.1 R88.1 SH1.2 U8.1(VDDIO) U8.14(VDD)
P3V3_KV10: C31.1 C32.1 C33.1 C34.1 J9.1(A1) J20.2 L3.2 R63.2 U13.1(VDD) U13.22(VDD)
P3V3_SDA: C8.1 C10.1 C12.1 C15.1 C17.1 C18.1 J10.1(A1) J18.1 R4.2 R12.1 R14.1 R17.1 R21.1 R23.1 R26.1 R27.2 R35.1 R36.1 R37.1 R61.2 U2.1(VCCA) U3.1(VCCA) U5.1(VDD1) U5.7(VDDA) U5.11(VBAT) U7.1(VCCA) U9.5(VCC) U10.7(VCCA) U12.1(VCCA)
P3V3_VREG: C51.1 D11.A J19.2 U17.2(VOUT) U17.4(TAB)
P5V0_SDA_USB_CONN_VBUS: J6.1(P1) L2.1 U1.1(A1)
P5V_OPT_VR: C53.1 D13.A J27.3
P5V_SDA: C1.1 C16.1 C19.1 L2.2 R5.1 R8.1 R34.1 R41.2 U5.6(VREGIN) U11.1(VIN)
P5V_SDA_PSW: D5.A D6.A R41.1 U11.6(VOUT)
P5V_USB: D5.C D13.C J3.10(B5)
VDDA: C30.1 C36.1 C39.1 L3.1 L9.2 U13.9(VDDA)
VSSA: C30.2 C36.2 C39.2 L8.1 L10.2 U13.12(VSSA)
ADC0_DM0: C35.1 J4.3(A2) J4.8(B4) R46.1 U13.8(ADC0_SE4/ADC0_DM0/PTE21/FTM1_CH1/UART0_RX)
ADC0_DP0: C22.1 J4.1(A1) J4.6(B3) R47.1 U13.7(ADC0_SE0/ADC0_DP0/PTE20/FTM1_CH0/UART0_TX)
ADC0_SE5/PTE17: C507.1 R551.1 U13.4(ADC0_SE5/ADC1_SE5/ADC0_DM1/PTE17/SPI0_SCK/UART1_RX/FTM_CLKIN1/LPTMR0_ALT3)
ADC0_SE5_RC: J2.7 R551.2
ADC0_SE6/PTE18: C505.1 R534.1 U13.5(ADC0_SE6/ADC1_SE1/ADC1_DP1/PTE18/SPI0_SOUT/UART1_CTS_b/I2C0_SDA/SPI0_SIN)
ADC0_SE6_RC: J2.1 R534.2
ADC0_SE7/PTE19: C44.1 R76.1 U13.6(ADC0_SE7/ADC1_SE7/ADC1_DM1/PTE19/SPI0_SIN/UART1_RTS_b/I2C0_SCL/SPI0_SOUT)
ADC0_SE7_RC: J2.5 R76.2
ADC0_SE9/PTB1: C516.1 R549.1 U13.28(ADC0_SE9/ADC1_SE9/PTB1/EWM_IN/FTM0_FLT2/I2C0_SDA/FTM1_CH1/FTM1_QD_PHB/UART0_TX)
ADC0_SE9_RC: J2.3 R549.2
ADC1_SE4/PTE30: C522.1 J4.11(A6) R555.1 U13.14(ADC1_SE4/CMP0_IN4/CMP1_IN4/DAC0_OUT/PTE30/FTM0_CH3/FTM_CLKIN1)
ADC1_SE4_RC: J2.9 R555.2
AREF: J2.16 R53.2
DC_JACK: D9.A J24.1(Pin)
FXOS8700CQ_CRST: C13.1 U8.8(CRST)
FXOS8700CQ_I2C_SA0: R31.1 R32.2 TP8.1(Pin1) U8.7(SA0/MISO)
FXOS8700CQ_I2C_SA1: R40.2 R43.1 TP11.1(Pin1) U8.10(SA1/~{CS})
LEDRGB_BLUE: D4.3(BLUE_C) R73.1 TP14.1(Pin1)
LEDRGB_GREEN: D4.4(GREEN_C) R74.1 TP17.1(Pin1)
LEDRGB_RED: D4.1(RED_C) R69.2 TP13.1(Pin1)
LVLRST_EN: R4.1 U3.5(OE)
MMA8451_BYP: C3.1 TP4.1(Pin1) U8.2(BYP)
P5-9V_VIN: C50.1 C52.1 C54.1 D10.A J3.16(B8) J27.1
P5-9V_VIN_VR: C41.1 D6.C D9.C D10.C U17.3(VIN)
POWER_EN: R29.1 U5.31(ADC0_SE7B/PTD6/SPI0_PCS3/UART0_RX/FTM0_CH6/FTM0_FLT0/LLWU_P15)
PTA1/FTM2_CH0: J3.3(A2) U13.18(PTA1/UART0_RX/FTM2_CH0/CMP0_OUT/FTM2_QD_PHA/FTM1_CH1)
PTA2/FTM2_CH1: J3.1(A1) U13.19(PTA2/UART0_TX/FTM2_CH1/CMP1_OUT/FTM2_QD_PHB/FTM1_CH0)
PTA4: C56.1 J2.4 R1.2 SW2.1(SW1) U13.21(PTA4/LLWU_P3/FTM0_CH1/FTM0_FLT3/NMI_b)
PTB0: C55.1 J1.10(B5) J1.11(A6) R75.2 SW3.1(SW1) U13.27(ADC0_SE8/ADC1_SE8/PTB0/LLWU_P5/I2C0_SCL/FTM1_CH0/FTM1_QD_PHA/UART0_RX)
PTB2: J2.15 J2.20 J4.7(A4) J4.12(B6) R50.2 R65.2 U8.9(INT2)
PTB3: J2.11 J2.18 J4.5(A3) J4.10(B5) R49.2 R66.1 U8.11(INT1)
PTC0: J4.2(B1) U13.33(ADC1_SE11/PTC0/SPI0_PCS4/PDB0_EXTRG/CMP0_OUT/FTM0_FLT0/SPI0_PCS0/SS_b)
PTC1/FTM0_CH0: J3.15(A8) U13.34(ADC1_SE3/PTC1/LLWU_P6/SPI0_PCS3/UART1_RTS_b/FTM0_CH0/FTM2_CH0)
PTC2/FTM0_CH1: J3.13(A7) U13.35(ADC0_SE11/CMP1_IN0/PTC2/SPI0_PCS2/UART1_CTS_b/FTM0_CH1/FTM2_CH1)
PTC3/FTM0_CH2: J3.11(A6) U13.36(CMP1_IN1/PTC3/LLWU_P7/SPI0_PCS1/UART1_RX/FTM0_CH2/CLKOUT)
PTC4/FTM0_CH3: J3.9(A5) U13.37(PTC4/LLWU_P8/SPI0_PCS0/SS_b/UART1_TX/FTM0_CH3/CMP1_OUT)
PTC5: J2.12 J2.17 J4.9(A5) U13.38(PTC5/LLWU_P9/SPI0_SCK/LPTMR0_ALT2/FTM0_CH2/CMP0_OUT)
PTC6: J2.13 R60.2 R67.2 U13.39(CMP0_IN0/PTC6/LLWU_P10/SPI0_SOUT/PDB0_EXTRG/UART0_RX/I2C0_SCL)
PTC6/I2C0_SCL: R9.2 R60.1 U8.4(SCL/SCLK)
PTC6/SPI0_SOUT: J2.8 R67.1
PTC7: J1.15(A8) J1.16(B8) R62.1 U13.40(CMP0_IN1/PTC7/SPI0_SIN/UART0_TX/I2C0_SDA)
PTC7/I2C0_SDA: R15.2 R62.2 U8.6(SDA/MOSI)
PTD0: J1.2(B1) J1.7(A4) R58.1
PTD1: J1.4(B2) J1.9(A5) R59.2 R64.2
PTD2: J2.2 U13.43(PTD2/LLWU_P13/SPI0_SOUT/UART0_RX/FTM0_CH2/I2C0_SCL)
PTD3: J2.19 R68.1 U13.44(PTD3/SPI0_SIN/UART0_TX/FTM0_CH3/I2C0_SDA)
PTD3/SPI0_SIN: J2.10 R68.2
PTD4/FTM0_CH4: J3.7(A4) U13.45(PTD4/LLWU_P14/SPI0_PCS1/UART0_RTS_b/FTM0_CH4/FTM2_CH0/EWM_IN)
PTD5/FTM0_CH5: J3.5(A3) U13.46(ADC0_SE3/PTD5/SPI0_PCS2/UART0_CTS_b/FTM0_CH5/FTM2_CH1/EWM_OUT_b)
PTD6: J2.6 R69.1 U13.47(ADC1_SE6/PTD6/LLWU_P15/SPI0_PCS3/UART0_RX/FTM0_CH0/FTM1_CH0/FTM0_FLT0)
PTD7: J1.3(A2) U13.48(PTD7/UART0_TX/FTM0_CH1/FTM1_CH1/FTM0_FLT1)
PTE16: J4.4(B2) U13.3(ADC0_SE1/ADC0_DP1/ADC1_SE0/PTE16/SPI0_PCS0/SS_b/UART1_TX/FTM_CLKIN0/FTM0_FLT3)
PTE24: J1.1(A1) J1.8(B4) U13.15(PTE24/FTM0_CH0/I2C0_SCL/EWM_OUT_b)
PTE25: J1.5(A3) J1.12(B6) R73.2 U13.16(PTE25/FTM0_CH1/I2C0_SDA/EWM_IN)
PTE29: J1.13(A7) J1.14(B7) R74.2 U13.13(CMP1_IN5/CMP0_IN5/PTE29/FTM0_CH2/FTM_CLKIN0)
RST_TGTMCU_B: D1.C(CATHODE) J3.6(B3) J9.10(B5) J25.3 R10.2 R11.2 U3.7(B1) U13.26(PTA20/RESET_b)
SDA_EXTAL: C9.1 U5.17(EXTAL0/PTA18/FTM0_FLT2/FTM_CLKIN0) Y1.3
SDA_JTAG_TCLK: J10.4(B2) U5.12(JTAG_TCLK/SWD_CLK/EZP_CLK/TSI0_CH1/PTA0/~{UART0_CTS}/~{UART0_COL}/FTM0_CH5)
SDA_JTAG_TDI: J10.8(B4) U5.13(JTAG_TDI/EZP_DI/TSI0_CH2/PTA1/UART0_RX/FTM0_CH6)
SDA_JTAG_TDO: J10.6(B3) U5.14(JTAG_TDO/TRACE_SWO/EZP_DO/TSI0_CH3/PTA2/UART0_TX/FTM0_CH7)
SDA_JTAG_TMS: J10.2(B1) R21.2 U5.15(JTAG_TMS/SWD_DIO/TSI0_CH4/PTA3/~{UART0_RTS}/FTM0_CH0)
SDA_LED: D2.C(CATHODE) U5.29(PTD4/SPI0_PCS1/~{UART0_RTS}/FTM0_CH4/EWM_IN/LLWU_P14)
SDA_LED_R: D2.A(ANODE) R17.2
SDA_RST: J10.10(B5) R5.2 R6.1 TP5.1(Pin1) U5.19(~{RESET})
SDA_RST_LED: D1.A(ANODE) R2.2
SDA_RST_TGTMCU_B: J5.2 U5.21(ADC0_SE9/TSI0_CH6/PTB1/I2C0_SDA/FTM1_CH1/FTM1_QD_PHB)
SDA_RST_TGTMCU_J_B: J5.1 J25.1 R10.1 R14.2 U3.2(A1)
SDA_RX_EN: R16.1 R23.2 U7.5(DIR)
SDA_SPI0_CS: R3.2 TP1.1(Pin1) U5.23(ADC0_SE4B/CMP1_IN0/TSI0_CH15/PTC2/SPI0_PCS2/~{UART1_CTS}/FTM0_CH1/I2S0_TX_FS)
SDA_SPI0_RST_B: R18.2 TP6.1(Pin1) U5.22(ADC0_SE15/TSI0_CH14/PTC1/SPI0_PCS3/~{UART1_RTS}/FTM0_CH0/I2S0_TXD0/LLWU_P6)
SDA_SPI0_SCK: U2.3(A) U5.26(PTC5/SPI0_SCK/LPTMR0_ALT2/I2S0_RXD0/CMP0_OUT/LLWU_P9)
SDA_SPI0_SIN: U5.28(CMP0_IN1/PTC7/SPI0_SIN/USB_SOF_OUT/I2S0_RX_FS) U10.5(2A)
SDA_SPI0_SOUT: U5.27(CMP0_IN0/PTC6/SPI0_SOUT/PDB0_EXTRG/I2S0_RX_BCLK/I2S0_MCLK/LLWU_P10) U12.3(A)
SDA_SWD_EN: R18.1 R19.1 U9.6(~{Y2})
SDA_SWD_EN_B: R25.2 U5.16(~{NMI}/~{EZP_CS}/TSI0_CH5/PTA4/FTM0_CH1/LLWU_P3)
SDA_SWD_EN_B_R: R25.1 R26.2 U9.1(A1)
SDA_SWD_EN_R: R12.2 R13.1 R19.2 U2.5(DIR)
SDA_SWD_OE: R3.1 R33.1 U9.4(~{Y1})
SDA_SWD_OE_B: R28.2 U5.20(ADC0_SE8/TSI0_CH0/PTB0/I2C0_SCL/FTM1_CH0/FTM1_QD_PHA/LLWU_P5)
SDA_SWD_OE_B_R: R27.1 R28.1 U9.3(A2)
SDA_SWD_OE_R: R33.2 R37.2 R39.1 U12.5(DIR)
SDA_USB_CONN_DN: J6.2(P2) R22.1 U4.1(A1)
SDA_USB_CONN_DP: J6.3(P3) R20.1 U6.1(A1)
SDA_USB_DN: R22.2 U5.4(USB0_DM)
SDA_USB_DP: R20.2 U5.3(USB0_DP)
SDA_USB_P5V_SENSE: R7.1 R8.2 U5.30(ADC0_SE6B/PTD5/SPI0_PCS2/~{UART0_CTS}/~{UART0_COL}/FTM0_CH5/~{EWM_OUT})
SDA_USBSHIELD: J6.S1(SHLD1) J6.S2(SHLD2) J6.S3(SHLD3) J6.S4(SHLD4) L1.1
SDA_VOUT33: C11.1 R36.2 U5.5(VOUT33)
SDA_XTAL: C6.1 U5.18(XTAL0/PTA19/FTM1_FLT0/FTM_CLKIN1/LPTMR0_ALT1) Y1.1
SW1_RST_B: C2.1 J25.2 SW1.2(SW2)
SWD_CLK_KV10: J11.1 U13.17(PTA0/UART0_CTS_b/FTM0_CH5/SWD_CLK)
SWD_CLK_TGTMCU: J8.2 J9.4(B2) J11.2
SWD_CLK_TGTMCU_BUF: J8.1 U2.4(B)
SWD_DIO_TGTMCU: J9.2(B1) J12.2 U13.20(PTA3/UART0_RTS_b/FTM0_CH0/FTM2_FLT0/EWM_OUT_b/SWD_DIO)
SWD_DIO_TGTMCU_BUF: J12.1 U10.2(2B) U12.4(B)
TC_EXTAL_TP: TP9.1(Pin1) U5.10(EXTAL32)
TC_SDA_USB_ID_TP: J6.4(P4) TP7.1(Pin1)
TC_XTAL_TP: TP10.1(Pin1) U5.9(XTAL32)
THER_A: C21.1 R45.2 R47.2 RT1.1
THER_B: C21.2 R44.1 R46.2 RT1.2
TP_2102_A: TP3.1(Pin1) U3.3(A2)
TP_2102_B: TP2.1(Pin1) U3.6(B2)
UART0_RX_TGTMCU: J1.6(B3) R24.2 R54.2
UART0_TX_TGTMCU: R38.2 R55.1
UART1_RX_TGTMCU_BUF: R24.1 U7.4(B)
UART1_RX_TGTMCU_R: U5.25(PTC4/SPI0_PCS0/UART1_TX/FTM0_CH3/CMP1_OUT/LLWU_P8) U7.3(A)
UART1_TX_TGTMCU_BUF: R38.1 U10.1(1B)
UART1_TX_TGTMCU_R: U5.24(CMP1_IN1/PTC3/SPI0_PCS1/UART1_RX/FTM0_CH2/I2S0_TX_BCLK/LLWU_P7) U10.6(1A)
V_TGTMCU: C7.1 C23.1 R2.1 R11.1 SH1.1 U2.6(VCCB) U3.8(VCCB) U7.6(VCCB) U10.8(VCCB) U12.6(VCCB)
VREFH: C29.1 C42.1 C43.1 L9.1 R53.1 U13.10(VREFH)
VREFL: C29.2 C42.2 C43.2 L10.1 U13.11(VREFL)
VTRG_EN: R29.2 R30.1 R34.2 U11.3(ENABLE)
VTRG_FAULT_B: R35.2 U5.32(PTD7/CMT_IRO/UART0_TX/FTM0_CH7/FTM0_FLT1) U11.4(~{FAULT})
N20314503: R42.1 R64.1 U8.16(RST)
N20662233: C19.2 U11.5(CSLEW)
N20923344: D4.2(COMMON_A) R88.2
N21117280: C24.2 QZ1.2 R52.1 U13.24(EXTAL0/PTA18/FTM0_FLT2/FTM_CLKIN0)
N21117910: C20.2 QZ1.1 R52.2 U13.25(XTAL0/PTA19/FTM0_FLT0/LPTMR0_ALT1/FTM1_FLT0/FTM_CLKIN1)
N21118289: R55.2 U13.32(PTB17/UART0_TX/FTM_CLKIN1/EWM_OUT_B)
N21118309: R54.1 U13.31(PTB16/UART0_RX/FTM_CLKIN2/EWM_IN)
N21120929: R58.2 U13.41(PTD0/LLWU_P12/SPI0_PCS0/SS_b/UART0_CTS_b/FTM0_CH0/UART1_RX)
N21120946: R59.1 U13.42(ADC0_SE2/PTD1/SPI0_SCK/UART0_RTS_b/FTM0_CH1/UART1_TX)
N21121221: R66.2 U13.30(ADC1_SE2/ADC1_DP2/PTB3/UART0_CTS_b/I2C0_SDA/FTM0_FLT0)
N21128407: R65.1 U13.29(ADC0_SE10/ADC1_SE10/ADC1_DM2/PTB2/I2C0_SCL/FTM0_FLT1/UART0_RTS_b/FTM0_FLT3)
N21239718: C51.2 R48.1

Not connected (* = marked no-connect by the designer): J3 2(B1)*; J9 6(B3)* 7(A4)* 8(B4)* 9(A5)*; J10 7(A4)* 9(A5)*; U8 15(NC)*

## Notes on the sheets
sheet 1
- Table of Contents
- Revisions & Change Log
- 1
- TITLE PAGE
- 2
- BLOCK DIAGRAM
- Rev
- Description
- Date
- Approved
- 3
- KV10 MCU
- A
- Initial Release
- 09-04-15
- 4
- OpenSDA INTERFACE
- 5
- ARDUINO SHIELDS
- A1
- Updated shunt location
- 01-16-15
- FRDM-KV10Z
- OrCAD Capture 16.5
sheet 2
- 1. Unless Otherwise Specified:
- All resistors are in ohms, most are 1%, 1/10 Watt.  Otherwise are 5%, 1/8 Watt.
- All capacitors are in uF, some are 10% or 20%
- All voltages are DC
- All polarized capacitors are tantalum
- 2. Interrupted lines coded with the same letter or letter
      combinations are electrically connected.
- 3. Device type number is for reference only. The number
      varies with the manufacturer.
- 4. Special signal usage:
- _B Denotes - Active-Low Signal
- <> or [] Denotes - Vectored Signals
- 5. Interpret diagram in accordance with American
  National Standards Institute specifications, current
  revision, with the exception of logic block symbology.
sheet 3
- KV10 - 48LQFP
- SERIAL RX/TX
  POKA-YOKE:
  Place both
  resistors
  with the same orientation
  and provide same airgap
  between RX to TX resistors
  terminals in a square fashion.
- TX
- TX
- RX
- RX
- NET NAMES
- PIN FUNCTIONS USED
- PIN FUNCTIONS USED
- NET NAMES
- SERIAL RX/TX
  POKA-YOKE:
  Place both
  resistors
  with the same orientation
  and provide same airgap
  between RX to TX resistors
  terminals in a square fashion.
- TX
- TX
- RX
- RX
- SWD CONNECTOR
- SHORTING HEADER ON BOTTOM LAYER
  Jumper is shorted by a cut-trace
  on bottom layer. Cutting the trace
  will effectively isolate the on-board
  MCU from the OpenSDA
  debug interface.
- 90C to -20C
- Vdiff ~ 0.372V to 2.879V
  (Ta=25C 1.650V)
- R
- G
- B
- LED FEATURE
- THERMISTOR
- RC Filter
sheet 4
- OpenSDA Interface
- RESET
- 1-2: Default.
  2-3: Reset signal direct to the MCU,
  to use when OpenSDA is not powered.
- RST Push Button
  Bypass
- TARGET MCU
  INTERFACE
  SIGNALS
- Output to system
  from Level shifter
- UART1_RX_TGTMCU
- Output to system
  from Level shifter
- Isolation
  Resistors
- UART1_TX_TGTMCU
- PU/PD LOGIC:
  SERIAL INTERFACE
  IS ALWAYS RESET
  WHEN USB PORT
  IS DISCONNECTED
- Output to system
  from Level shifter
- SWD_DIO_TGTMCU
- OPEN SDA
  POWER OUTPUTS
- HW Designer: Rafael del Rey
- OPEN SDA
  INPUT POWER
- i
- path
- i
- path
- Note: Lower Cost Alternative to PWR switch:
  Populate R41
  DNP: U11, R30, R29, C19, C16
  Leave R35 populated to prevent a floating input on U5
- Note: You can power openSDA
  with your own power supplies
  by replacing this rail
  (SDA_VOUT33)
  with your 3.3V power supply rail
- 3.3VDC, 10mA should be provided
  to this rail (P3V3_SDA)
  in order to power openSDA
  module
- OpenSDA INTERFACE JTAG CONNECTOR
- PWR SWITCH
- (To enable 5v from
  USB connector)
- Isolation and level shift stage
  (for 1.8 to 5V compatibility)
- PU/PD LOGIC (DIR PIN):
  BUFFER IS TRISTATED WHEN
  P3V3_SDA IS UNPOWERED
- i
- path
- SDA_VOUT33 can provide up to 120mA
  of power at 3.3VDC to your system
  P5V_TRG_SDA can provide up to 450mA
  (per USB spec) of power at 5VDC
  to your system
- ACTIVE HIGH
- I/O POWER
  INPUT
- i
- path
- V_BRD is supported
  from 1.8V to 5V
- Power should be provided
  to this rail for the logic
  related to your platform I/O
- {For enablement purposes only}
sheet 5
- I2C INERTIAL SENSOR
- ( ACCELEROMETER AND MAGNETOMETER )
- SHORTING HEADER
  ON BOTTOM LAYER
- SHORTING HEADER
  ON BOTTOM LAYER
- ARDUINO COMPATIBLE HEADERS
- Default I2C Slave Address:
        0011101 (0x1D)
- SAMTEC
  ESQ-110-23-T-D
- SAMTEC
  ESQ-108-23-T-D
- INTERRUPTS
- 5VDC VR
  SUPPORT
- SAMTEC
  ESQ-108-23-T-D
- IN
- OUT
- SAMTEC
  ESQ-106-23-T-D
- DEBUG GROUND HOOK
- IF YOUR 5V LDO
  HAS BACKFEED PROTECTION
  JUST SHUNT
  THIS DIODE FOOTPRINT
- SDA
- SCL
